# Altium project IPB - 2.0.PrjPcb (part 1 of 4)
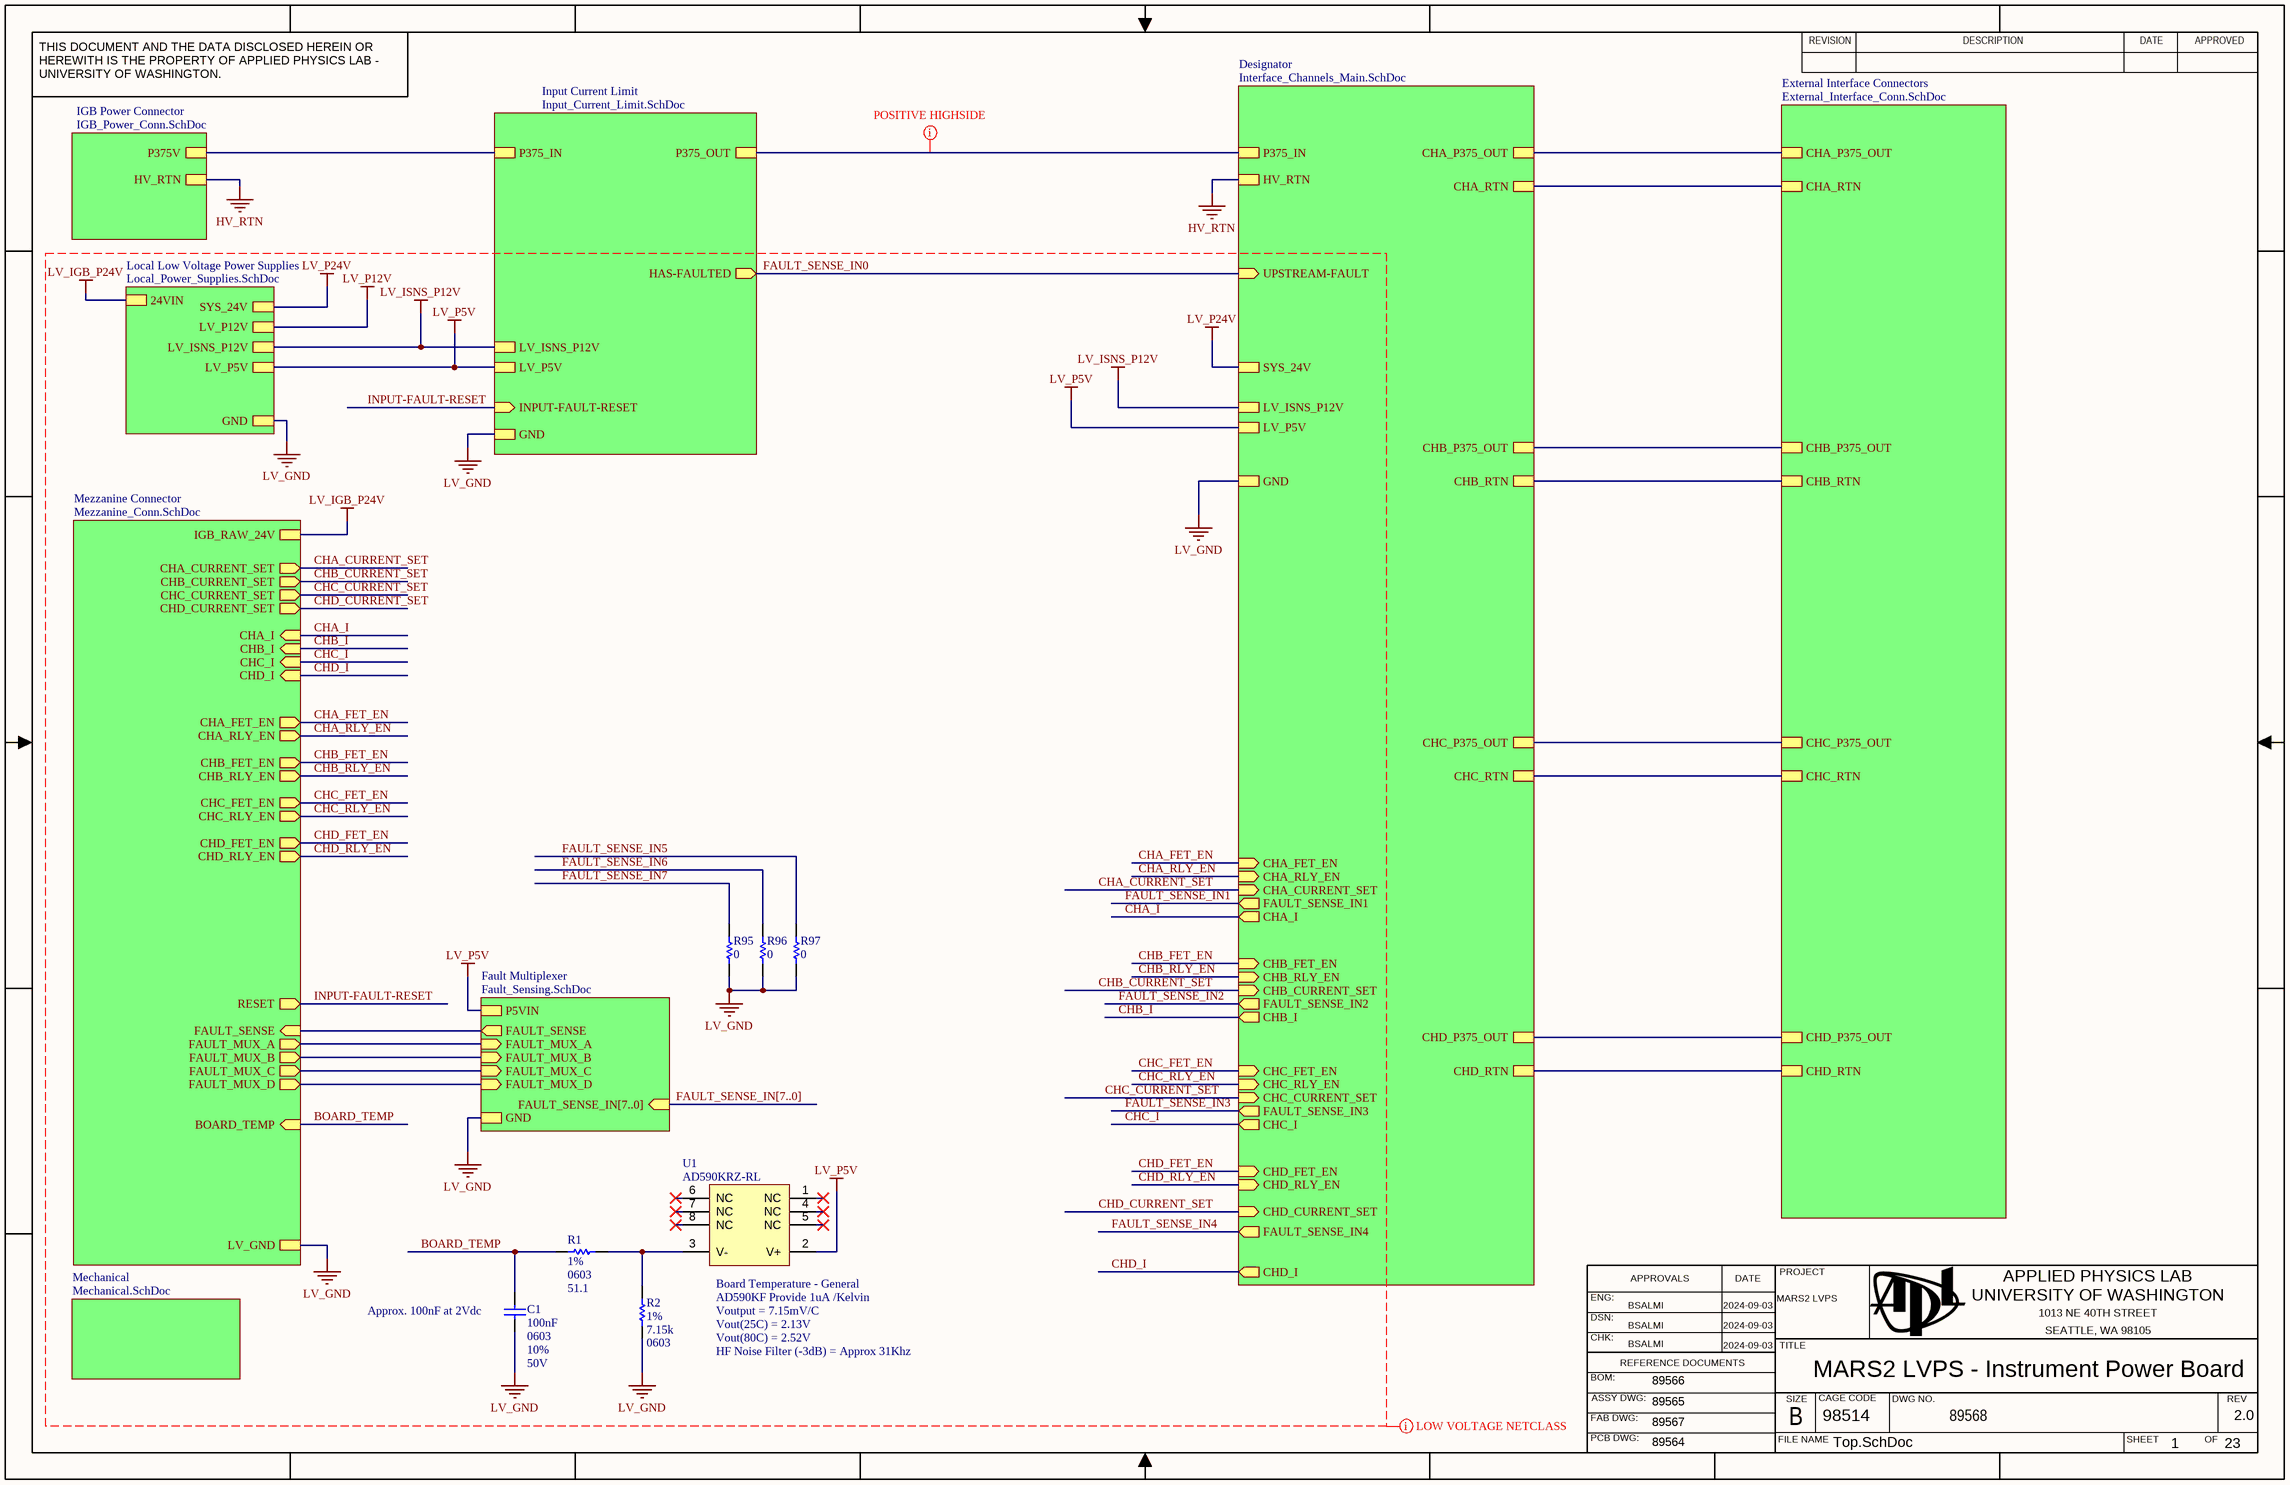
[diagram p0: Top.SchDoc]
Gbl_Cage: 98514; Gbl_CheckedBy: BSALMI; Gbl_CHK_APP_DATE: 2024-09-03; Gbl_DOC_NO_ASSY_DWG: 89565; Gbl_DOC_NO_BOM: 89566; Gbl_DOC_NO_FAB_DWG: 89567; Gbl_DOC_NO_SCH_DWG: 89568; Gbl_DrawnBy: BSALMI; Gbl_DSN_APP_DATE: 2024-09-03; Gbl_ENG_APP_DATE: 2024-09-03; Gbl_Engineer: BSALMI; Gbl_PCB_DWG_NO: 89564; Gbl_Project: MARS2 LVPS; Gbl_Revision: 2.0; GlobalCage: 98514; GlobalProject: MARS2 LVPS; GlobalRevision: 2.0; GlobalSchematicNumber: 89568
23 sheets, 657 parts. Net scope: strictly hierarchical (ports join the sheet entries above them; power ports are local).
Board file: IPB_V2.PcbDoc
Sheets:
  Top.SchDoc
    IGB Power Connector = IGB_Power_Conn.SchDoc
    Input Current Limit = Input_Current_Limit.SchDoc
      Current Sense = Current_Sense.SchDoc
      Current Limit - Configurable = Analog_Current_Limit.SchDoc
      12V to 5V (Linear) - ISNS Power = 12V_to_5V_ISNS_REFOUT.SchDoc
      Channel Logic = FET_CH_Digital_Logic.SchDoc
    Mezzanine Connector = Mezzanine_Conn.SchDoc
    External Interface Connectors = External_Interface_Conn.SchDoc
    Fault Multiplexer = Fault_Sensing.SchDoc
    Local Low Voltage Power Supplies = Local_Power_Supplies.SchDoc
      24 to 12V (DC/DC) = 24V_to_12V_DCDC.SchDoc
      24 to 5V (DC/DC) - 5V Logic = 24V_to_5V_DCDC.SchDoc
    Mechanical = Mechanical.SchDoc
    Designator = Interface_Channels_Main.SchDoc
      Interface Channel A = Interface_Channel.SchDoc
        Overcurrent Current Sense = Current_Sense.SchDoc
        Channel Logic = FET_CH_Digital_Logic.SchDoc
        Current Limit - Configurable = Analog_Current_Limit.SchDoc
        Contactor Driver = Relay_Driver.SchDoc
        Contactor Driver = Relay_Driver.SchDoc
        Anti-Alias Filter = Anti_Alias_Filter.SchDoc
        12V to 5V (Linear) - ISNS Power = 12V_to_5V_ISNS_REFOUT.SchDoc
        Solid State Switches = Solid_State_Switch.SchDoc
          Isolated Gate Drive Power - HIGH = Isolated_Gate_Power_Supplies.SchDoc
          Short Circuit Current Sense = IN310_ISNS.SchDoc
          Short Circuit Logic Intergration = Short-Circuit-Logic-Integration.SchDoc
            MOSFET HIGH Driver = Gate_Driver.SchDoc
      Interface Channel B = Interface_Channel.SchDoc
        Overcurrent Current Sense = Current_Sense.SchDoc
        Channel Logic = FET_CH_Digital_Logic.SchDoc
        Current Limit - Configurable = Analog_Current_Limit.SchDoc
        Contactor Driver = Relay_Driver.SchDoc
        Contactor Driver = Relay_Driver.SchDoc
        Anti-Alias Filter = Anti_Alias_Filter.SchDoc
        12V to 5V (Linear) - ISNS Power = 12V_to_5V_ISNS_REFOUT.SchDoc
        Solid State Switches = Solid_State_Switch.SchDoc
          Isolated Gate Drive Power - HIGH = Isolated_Gate_Power_Supplies.SchDoc
          Short Circuit Current Sense = IN310_ISNS.SchDoc
          Short Circuit Logic Intergration = Short-Circuit-Logic-Integration.SchDoc
            MOSFET HIGH Driver = Gate_Driver.SchDoc
      Interface Channel C = Interface_Channel.SchDoc
        Overcurrent Current Sense = Current_Sense.SchDoc
        Channel Logic = FET_CH_Digital_Logic.SchDoc
        Current Limit - Configurable = Analog_Current_Limit.SchDoc
        Contactor Driver = Relay_Driver.SchDoc
        Contactor Driver = Relay_Driver.SchDoc
        Anti-Alias Filter = Anti_Alias_Filter.SchDoc
        12V to 5V (Linear) - ISNS Power = 12V_to_5V_ISNS_REFOUT.SchDoc
        Solid State Switches = Solid_State_Switch.SchDoc
          Isolated Gate Drive Power - HIGH = Isolated_Gate_Power_Supplies.SchDoc
          Short Circuit Current Sense = IN310_ISNS.SchDoc
          Short Circuit Logic Intergration = Short-Circuit-Logic-Integration.SchDoc
            MOSFET HIGH Driver = Gate_Driver.SchDoc
      Interface Channel D = Interface_Channel.SchDoc
        Overcurrent Current Sense = Current_Sense.SchDoc
        Channel Logic = FET_CH_Digital_Logic.SchDoc
        Current Limit - Configurable = Analog_Current_Limit.SchDoc
        Contactor Driver = Relay_Driver.SchDoc
        Contactor Driver = Relay_Driver.SchDoc
        Anti-Alias Filter = Anti_Alias_Filter.SchDoc
        12V to 5V (Linear) - ISNS Power = 12V_to_5V_ISNS_REFOUT.SchDoc
        Solid State Switches = Solid_State_Switch.SchDoc
          Isolated Gate Drive Power - HIGH = Isolated_Gate_Power_Supplies.SchDoc
          Short Circuit Current Sense = IN310_ISNS.SchDoc
          Short Circuit Logic Intergration = Short-Circuit-Logic-Integration.SchDoc
            MOSFET HIGH Driver = Gate_Driver.SchDoc

## Sheet Top.SchDoc: MARS2 LVPS - Instrument Power Board
size 431 x 279 mm; Organization: ORGANIZATION; Address1: APPLIED PHYSICS LAB; Address2: UNIVERSITY OF WASHINGTON; Address3: 1013 NE 40TH STREET; Address4: SEATTLE, WA 98105; Revision: -; SheetNumber: 1; SheetTotal: 23; ENG_APP_DATE: --/--/--; DSN_APP_DATE: --/--/--; CHK_APP_DATE: --/--/--

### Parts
C1  value 100nF  Case/Package: 0603  Tolerance: 10%  Voltage Rating: 50V  [CAPC1608X90X40ML10T20]  (hidden comment: Capacitor 100nF +/- 10%, 50V, X7R, 0603)
R1  value 51.1  Tolerance: 1%  Case/Package: 0603  [RESC1609X50X30ML08T20]  (hidden comment: Resistor 51R1 +/-1% 0603 100 mW)
R2  value 7.15k  Tolerance: 1%  Case/Package: 0603  [RESC1609X50X30ML08T20]  (hidden comment: Resistor 7K15 +/-1% 0603 100 mW)
R95  value 0  [RESC1608X55X25ML10T15]  (hidden comment: Resistor 0R +/- 5% 0603 100 mW)
R96  value 0  [RESC1608X55X25ML10T15]  (hidden comment: Resistor 0R +/- 5% 0603 100 mW)
R97  value 0  [RESC1608X55X25ML10T15]  (hidden comment: Resistor 0R +/- 5% 0603 100 mW)
U1  AD590KRZ-RL  [ADI-R-8_M]

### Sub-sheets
Designator = Interface_Channels_Main.SchDoc: CHA_P375_OUT, CHB_P375_OUT, CHC_P375_OUT, CHD_P375_OUT, CHA_RTN, CHB_RTN, CHC_RTN, CHD_RTN, P375_IN, HV_RTN, UPSTREAM-FAULT (in), CHD_FET_EN (in), CHD_RLY_EN (in), CHD_CURRENT_SET (in), FAULT_SENSE_IN4 (out), CHD_I (out), CHC_FET_EN (in), CHC_RLY_EN (in), CHC_CURRENT_SET (in), FAULT_SENSE_IN3 (out), CHC_I (out), CHB_FET_EN (in), CHB_RLY_EN (in), CHB_CURRENT_SET (in), FAULT_SENSE_IN2 (out), CHB_I (out), CHA_FET_EN (in), CHA_RLY_EN (in), CHA_CURRENT_SET (in), FAULT_SENSE_IN1 (out), CHA_I (out), SYS_24V, LV_ISNS_P12V, LV_P5V, GND
External Interface Connectors = External_Interface_Conn.SchDoc: CHA_P375_OUT, CHB_P375_OUT, CHC_P375_OUT, CHD_P375_OUT, CHA_RTN, CHB_RTN, CHC_RTN, CHD_RTN
Fault Multiplexer = Fault_Sensing.SchDoc: FAULT_SENSE (out), FAULT_SENSE_IN[7..0] (in), FAULT_MUX_D (in), FAULT_MUX_B (in), FAULT_MUX_A (in), FAULT_MUX_C (in), GND, P5VIN
IGB Power Connector = IGB_Power_Conn.SchDoc: P375V, HV_RTN
Input Current Limit = Input_Current_Limit.SchDoc: P375_IN, P375_OUT, HAS-FAULTED (out), INPUT-FAULT-RESET (in), LV_P5V, LV_ISNS_P12V, GND
Local Low Voltage Power Supplies = Local_Power_Supplies.SchDoc: 24VIN, SYS_24V, LV_P12V, LV_ISNS_P12V, LV_P5V, GND
Mechanical = Mechanical.SchDoc: no entries
Mezzanine Connector = Mezzanine_Conn.SchDoc: CHB_CURRENT_SET (out), CHA_CURRENT_SET (out), CHC_CURRENT_SET (out), CHD_CURRENT_SET (out), CHB_I (in), CHD_I (in), CHC_I (in), CHA_I (in), BOARD_TEMP (in), FAULT_SENSE (in), RESET (out), CHA_RLY_EN (out), CHC_RLY_EN (out), CHA_FET_EN (out), CHC_FET_EN (out), CHD_FET_EN (out), CHD_RLY_EN (out), CHB_RLY_EN (out), CHB_FET_EN (out), FAULT_MUX_A (out), FAULT_MUX_B (out), FAULT_MUX_C (out), FAULT_MUX_D (out), LV_GND, IGB_RAW_24V

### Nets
HV_RTN: sheet IGB Power Connector/HV_RTN, sheet Designator/HV_RTN  [project net N187]
LV_GND: C1.1 R2.1 R95.1 R96.1 R97.1 ; sheet Input Current Limit/GND, sheet Mezzanine Connector/LV_GND, sheet Fault Multiplexer/GND, sheet Local Low Voltage Power Supplies/GND, sheet Designator/GND
LV_IGB_P24V: sheet Mezzanine Connector/IGB_RAW_24V, sheet Local Low Voltage Power Supplies/24VIN
LV_ISNS_P12V: sheet Input Current Limit/LV_ISNS_P12V, sheet Local Low Voltage Power Supplies/LV_ISNS_P12V, sheet Designator/LV_ISNS_P12V
LV_P5V: U1.2(V+) ; sheet Input Current Limit/LV_P5V, sheet Fault Multiplexer/P5VIN, sheet Local Low Voltage Power Supplies/LV_P5V, sheet Designator/LV_P5V
LV_P24V: sheet Local Low Voltage Power Supplies/SYS_24V, sheet Designator/SYS_24V  [project net COIL_DRV_HIGH]
BOARD_TEMP: C1.2 R1.1 ; sheet Mezzanine Connector/BOARD_TEMP
CHA_CURRENT_SET: sheet Mezzanine Connector/CHA_CURRENT_SET, sheet Designator/CHA_CURRENT_SET
CHA_FET_EN: sheet Mezzanine Connector/CHA_FET_EN, sheet Designator/CHA_FET_EN
CHA_I: sheet Mezzanine Connector/CHA_I, sheet Designator/CHA_I
CHA_RLY_EN: sheet Mezzanine Connector/CHA_RLY_EN, sheet Designator/CHA_RLY_EN
CHB_CURRENT_SET: sheet Mezzanine Connector/CHB_CURRENT_SET, sheet Designator/CHB_CURRENT_SET
CHB_FET_EN: sheet Mezzanine Connector/CHB_FET_EN, sheet Designator/CHB_FET_EN
CHB_I: sheet Mezzanine Connector/CHB_I, sheet Designator/CHB_I
CHB_RLY_EN: sheet Mezzanine Connector/CHB_RLY_EN, sheet Designator/CHB_RLY_EN
CHC_CURRENT_SET: sheet Mezzanine Connector/CHC_CURRENT_SET, sheet Designator/CHC_CURRENT_SET
CHC_FET_EN: sheet Mezzanine Connector/CHC_FET_EN, sheet Designator/CHC_FET_EN
CHC_I: sheet Mezzanine Connector/CHC_I, sheet Designator/CHC_I
CHC_RLY_EN: sheet Mezzanine Connector/CHC_RLY_EN, sheet Designator/CHC_RLY_EN
CHD_CURRENT_SET: sheet Mezzanine Connector/CHD_CURRENT_SET, sheet Designator/CHD_CURRENT_SET
CHD_FET_EN: sheet Mezzanine Connector/CHD_FET_EN, sheet Designator/CHD_FET_EN
CHD_I: sheet Mezzanine Connector/CHD_I, sheet Designator/CHD_I
CHD_RLY_EN: sheet Mezzanine Connector/CHD_RLY_EN, sheet Designator/CHD_RLY_EN
FAULT_MUX_A: sheet Mezzanine Connector/FAULT_MUX_A, sheet Fault Multiplexer/FAULT_MUX_A
FAULT_MUX_B: sheet Mezzanine Connector/FAULT_MUX_B, sheet Fault Multiplexer/FAULT_MUX_B
FAULT_MUX_C: sheet Mezzanine Connector/FAULT_MUX_C, sheet Fault Multiplexer/FAULT_MUX_C
FAULT_MUX_D: sheet Mezzanine Connector/FAULT_MUX_D, sheet Fault Multiplexer/FAULT_MUX_D
FAULT_SENSE: sheet Mezzanine Connector/FAULT_SENSE, sheet Fault Multiplexer/FAULT_SENSE
FAULT_SENSE_IN0: sheet Input Current Limit/HAS-FAULTED, sheet Designator/UPSTREAM-FAULT
FAULT_SENSE_IN5: R97.2
FAULT_SENSE_IN6: R96.2
FAULT_SENSE_IN7: R95.2
INPUT-FAULT-RESET: sheet Input Current Limit/INPUT-FAULT-RESET, sheet Mezzanine Connector/RESET
P187: sheet IGB Power Connector/P375V, sheet Input Current Limit/P375_IN
NetD1_A_1: sheet External Interface Connectors/CHA_RTN, sheet Designator/CHA_RTN
NetD1_A_4: sheet External Interface Connectors/CHA_P375_OUT, sheet Designator/CHA_P375_OUT
NetD1_B_1: sheet External Interface Connectors/CHB_RTN, sheet Designator/CHB_RTN
NetD1_B_4: sheet External Interface Connectors/CHB_P375_OUT, sheet Designator/CHB_P375_OUT
NetD1_C_1: sheet External Interface Connectors/CHC_RTN, sheet Designator/CHC_RTN
NetD1_C_4: sheet External Interface Connectors/CHC_P375_OUT, sheet Designator/CHC_P375_OUT
NetD1_D_1: sheet External Interface Connectors/CHD_RTN, sheet Designator/CHD_RTN
NetD1_D_4: sheet External Interface Connectors/CHD_P375_OUT, sheet Designator/CHD_P375_OUT
NetR1_2: R1.2 R2.2 U1.3(V-)
NetU4_A_3: sheet Input Current Limit/P375_OUT, sheet Designator/P375_IN

Not connected (* = marked no-connect by the designer): U1 1(NC)* 4(NC)* 5(NC)* 6(NC)* 7(NC)* 8(NC)*

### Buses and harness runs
bus FAULT_SENSE_IN[7..0] = sheet Fault Multiplexer/FAULT_SENSE_IN[7..0]

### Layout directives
net class LV_NETCLASS: BOARD_TEMP, CHA_CURRENT_SET, CHA_FET_EN, CHA_I, CHA_RLY_EN, CHB_CURRENT_SET, CHB_FET_EN, CHB_I, CHB_RLY_EN, CHC_CURRENT_SET, CHC_FET_EN, CHC_I, CHC_RLY_EN, CHD_CURRENT_SET, CHD_FET_EN, CHD_I, CHD_RLY_EN, FAULT_SENSE_IN0, FAULT_SENSE_IN1, FAULT_SENSE_IN2, FAULT_SENSE_IN3, FAULT_SENSE_IN4, FAULT_SENSE_IN5, FAULT_SENSE_IN6, FAULT_SENSE_IN7, FAULT_SENSE_IN[7..0], INPUT-FAULT-RESET, LV_GND, LV_IGB_P24V, LV_ISNS_P12V, LV_P5V, LV_P12V, LV_P24V
net class POSITIVE HIGHSIDE: NetU4_A_3

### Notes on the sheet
- (near U1) Board Temperature - General
- (near U1) AD590KF Provide 1uA /Kelvin
- (near C1) Approx. 100nF at 2Vdc
- Voutput = 7.15mV/C
- Vout(25C) = 2.13V
- Vout(80C) = 2.52V
- HF Noise Filter (-3dB) = Approx 31Khz

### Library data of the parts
C1 = CMP-001-00206-10: Chip Capacitor, 100nF, +/- 10%, 50 V, X7R 0603 (1608 Metric); Capacitor Type: Ceramic
R1 = CMP-009-01135-2: Chip Resistor, 51.1 Ohm, +/- 1%, 0.1 W, -55 to 155 degC, 0603 (1608 Metric); Voltage Rating: 75V; Power: 100mW; Decade: 10
R2 = CMP-009-00865-5: Chip Resistor, 7.15k Ohm, +/- 1%, 0.1 W, -55 to 155 degC, 0603 (1608 Metric); Voltage Rating: 75V; Power: 100mW; Decade: 1k
R95-R97 = CMP-009-00006-7: Chip Resistor, 0 Ohm, 0.1 W, -55 to 155 degC, 0603 (1608 Metric); Voltage Rating: 50V; Power: 100mW
U1 = CMP-010-00032-1: Temp Sensor Analog 8-Pin SOIC N T/R; Max Supply Voltage: 30V; Min Supply Voltage: 4V

## Sheet IGB_Power_Conn.SchDoc: MARS2 - IPB - IGB Power Conn
size 431 x 279 mm; Organization: ORGANIZATION; Address1: APPLIED PHYSICS LAB; Address2: UNIVERSITY OF WASHINGTON; Address3: 1013 NE 40TH STREET; Address4: SEATTLE, WA 98105; Revision: -; SheetNumber: 2; SheetTotal: 23; ENG_APP_DATE: --/--/--; DSN_APP_DATE: --/--/--; CHK_APP_DATE: --/--/--
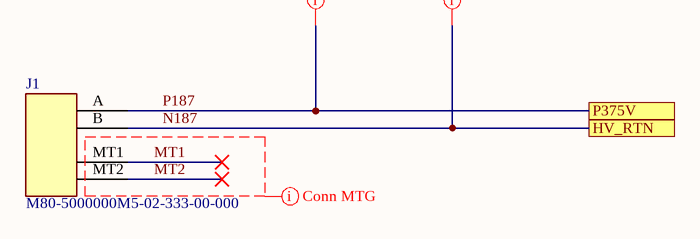
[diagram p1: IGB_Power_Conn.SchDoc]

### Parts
J1  M80-5000000M5-02-333-00-000  [FP-M80-5000000M5-02-333-0-MFG]

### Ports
HV_RTN, P375V

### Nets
N187: J1.B ; port HV_RTN
MT1: J1.MT1(MNT_1)  [project net MT1_2]
MT2: J1.MT2(MNT_2)  [project net MT2_2]
P187: J1.A ; port P375V

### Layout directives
net class P187_REF: P187
net class N187_REF: N187
net class Mounting Hole: MT1, MT2

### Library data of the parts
J1 = CMP-002-00075-7: Conn Header R/a 2POS 4MM; Manufacturer: Harwin; Number of Positions: 2; Pitch: 4.00mm; Current Rating: 40A; Contact Resistance: 25mR; Voltage Rating: 800V; Gender: Male; Insulation Resistance: 100MR

## Sheet Input_Current_Limit.SchDoc: MARS2 - IPB - Input Current Limit
size 431 x 279 mm; Organization: ORGANIZATION; Address1: APPLIED PHYSICS LAB; Address2: UNIVERSITY OF WASHINGTON; Address3: 1013 NE 40TH STREET; Address4: SEATTLE, WA 98105; Revision: -; SheetNumber: 4; SheetTotal: 23; ENG_APP_DATE: --/--/--; DSN_APP_DATE: --/--/--; CHK_APP_DATE: --/--/--
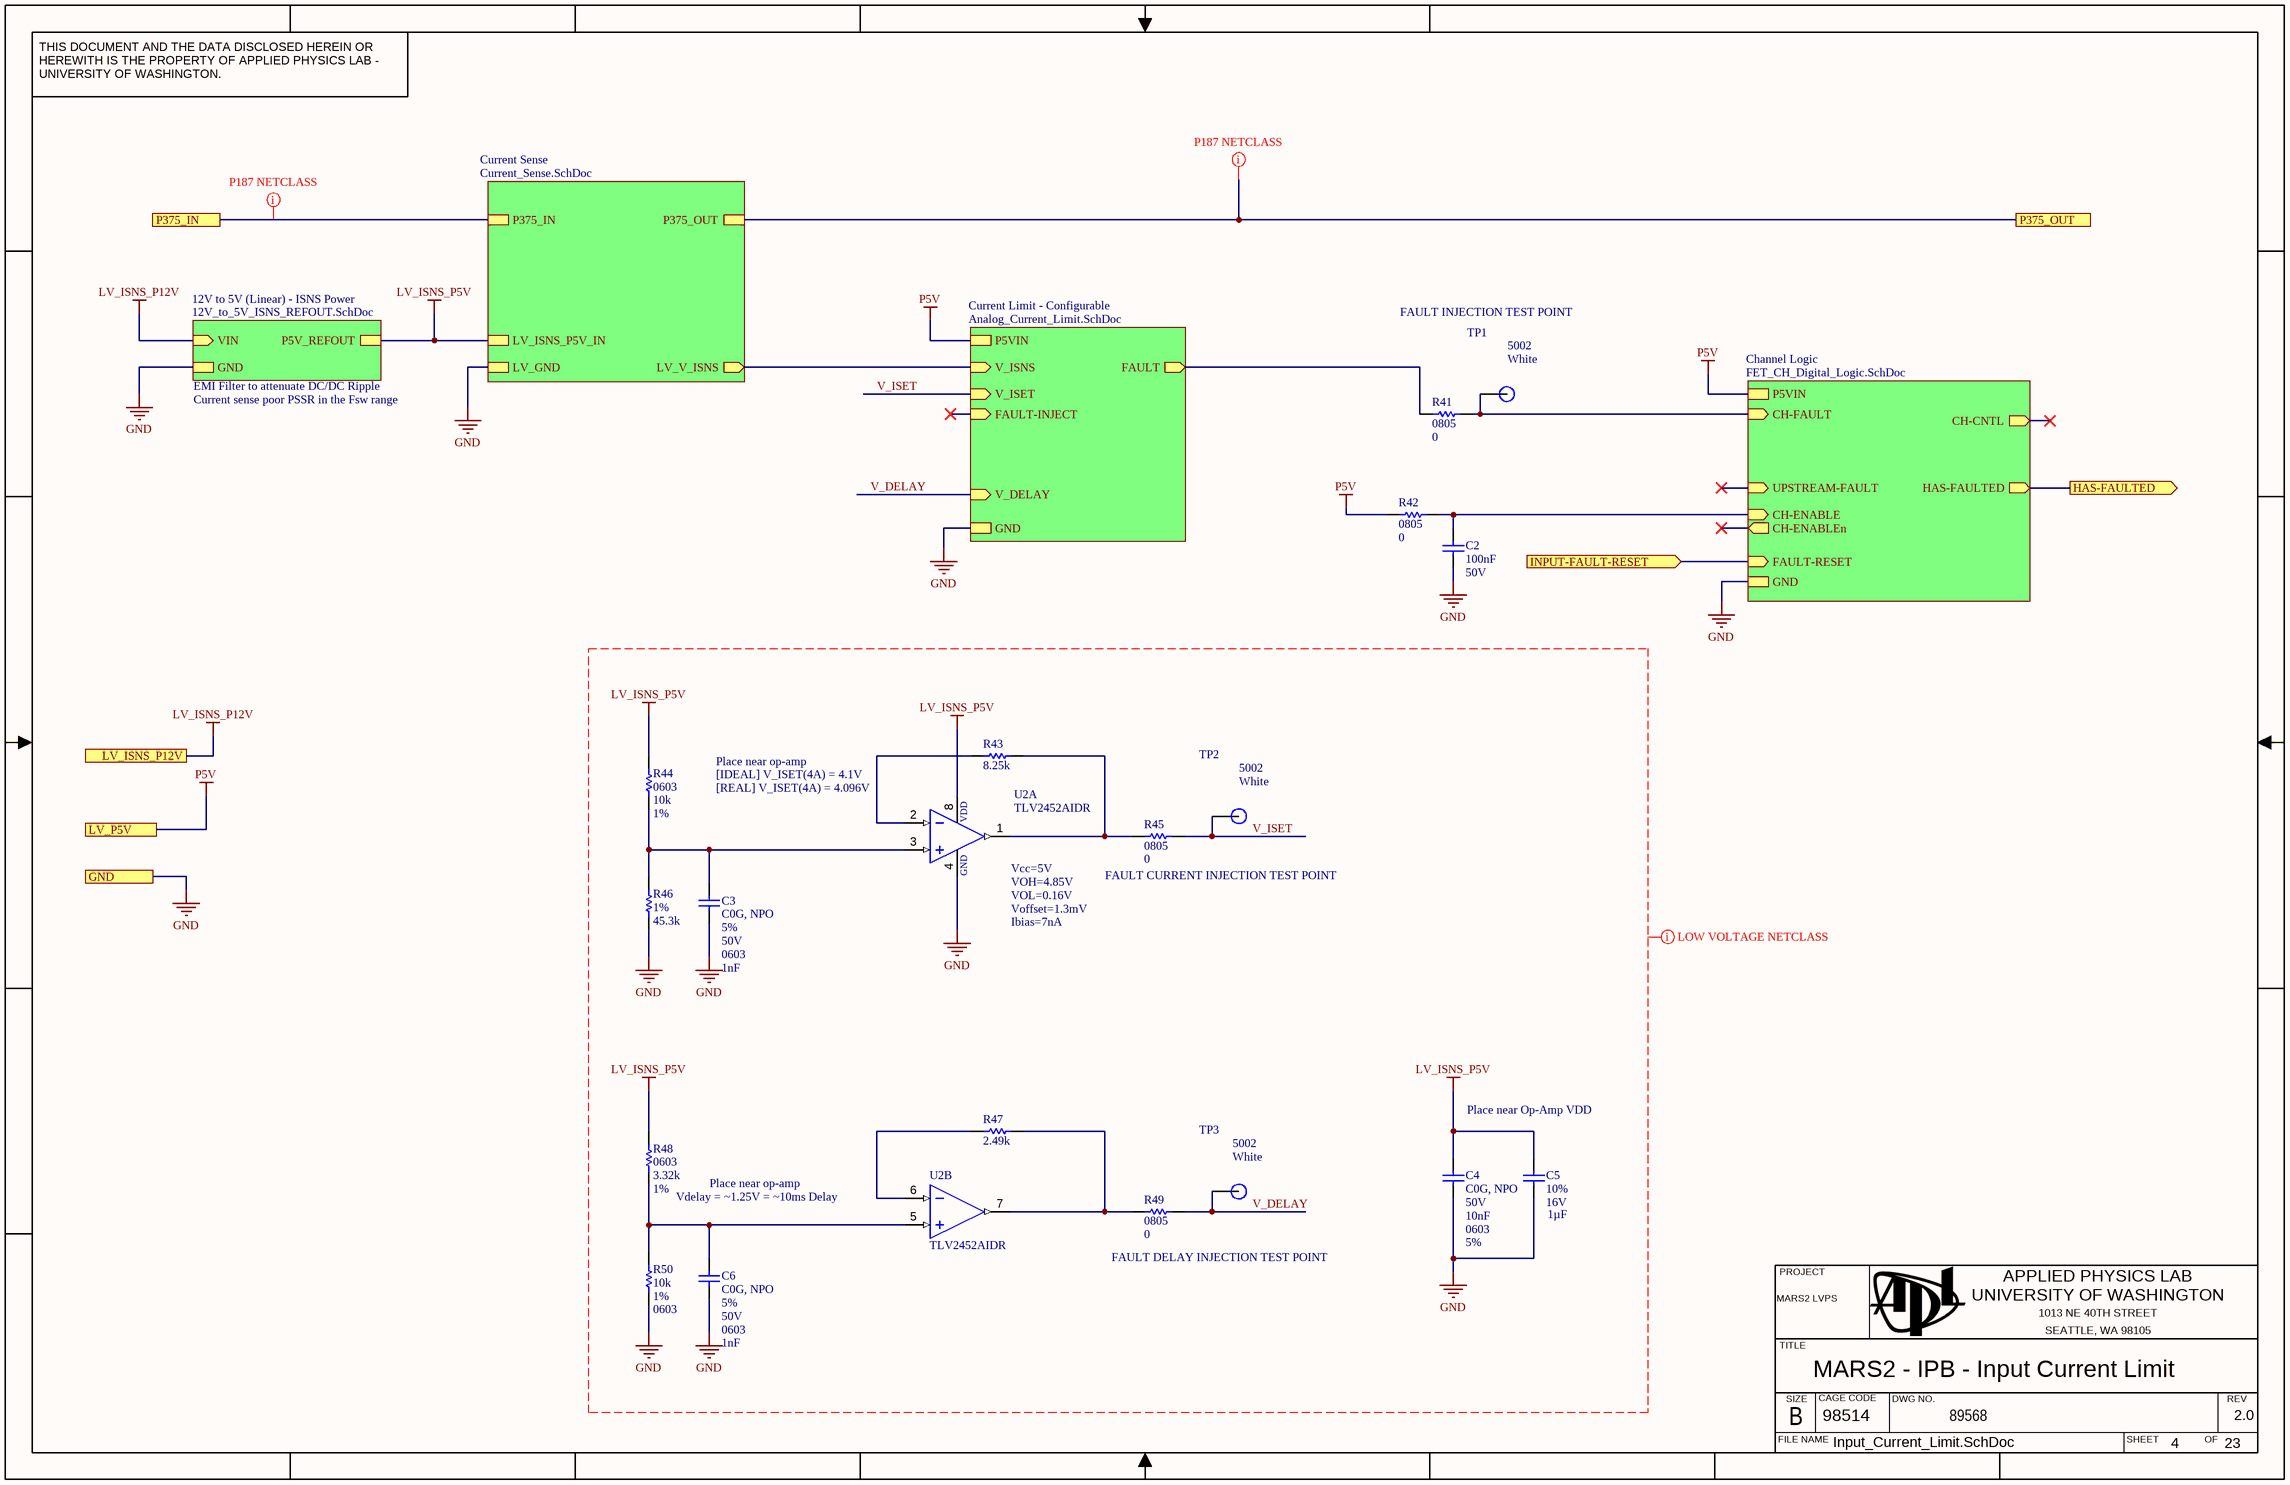
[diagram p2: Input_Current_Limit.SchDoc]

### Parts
C2  value 100nF  Voltage Rating: 50V  [CAPC2013X95X50ML10T25]  (hidden comment: Capacitor 100 nF +/-10% 50 V 0805)
C3  Dielectric: C0G, NPO  Tolerance: 5%  Voltage Rating: 50V  Case/Package: 0603  Capacitance: 1nF  [CAPC1608X90X40ML10T20]  (hidden comment: Capacitor 1nF +/- 5%, 50V, C0G, 0603)
C4  Dielectric: C0G, NPO  Voltage Rating: 50V  Capacitance: 10nF  Case/Package: 0603  Tolerance: 5%  [CAPC1608X90X40ML10T20]  (hidden comment: Capacitor 10nF +/- 5%, 50V, C0G, 0603)
C5  value 1µF  Tolerance: 10%  Voltage Rating: 16V  [CAPC1608X94X35NL15T15]  (hidden comment: Capacitor 1 uF +/- 10% 16 V 0603)
C6  Dielectric: C0G, NPO  Tolerance: 5%  Voltage Rating: 50V  Case/Package: 0603  Capacitance: 1nF  [CAPC1608X90X40ML10T20]  (hidden comment: Capacitor 1nF +/- 5%, 50V, C0G, 0603)
R41  value 0  Case/Package: 0805  [RESC2013X60X35ML10T20]  (hidden comment: Resistor 0R +/- 5% 0805 125 mW)
R42  value 0  Case/Package: 0805  [RESC2013X60X35ML10T20]  (hidden comment: Resistor 0R +/- 5% 0805 125 mW)
R43  value 8.25k  [RESC1609X50X30ML08T20]  (hidden comment: Resistor 8K25 +/-1% 0603 100 mW)
R44  value 10k  Case/Package: 0603  Tolerance: 1%  [RESC1608X55X25ML10T15]  (hidden comment: Resistor 10k +/-1% 0603 100 mW)
R45  value 0  Case/Package: 0805  [RESC2013X60X35ML10T20]  (hidden comment: Resistor 0R +/- 5% 0805 125 mW)
R46  value 45.3k  Tolerance: 1%  [RESC1608X55X25ML10T15]  (hidden comment: Resistor 45K3 +/-1% 0603 100 mW)
R47  value 2.49k  [RESC1609X50X30ML08T20]  (hidden comment: Resistor 2K49 +/-1% 0603 100 mW)
R48  value 3.32k  Case/Package: 0603  Tolerance: 1%  [RESC1609X50X30ML08T20]  (hidden comment: Resistor 3K32 +/-1% 0603 100 mW)
R49  value 0  Case/Package: 0805  [RESC2013X60X35ML10T20]  (hidden comment: Resistor 0R +/- 5% 0805 125 mW)
R50  value 10k  Tolerance: 1%  Case/Package: 0603  [RESC1608X55X25ML10T15]  (hidden comment: Resistor 10k +/-1% 0603 100 mW)
TP1  5002  Color: White  [Keystone 5002]
TP2  5002  Color: White  [Keystone 5002]
TP3  5002  Color: White  [Keystone 5002]
U2  TLV2452AIDR  [D0008A_L]  (parts A,B of 2)

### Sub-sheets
12V to 5V (Linear) - ISNS Power = 12V_to_5V_ISNS_REFOUT.SchDoc: VIN (in), P5V_REFOUT, GND
Channel Logic = FET_CH_Digital_Logic.SchDoc: CH-FAULT (in), CH-CNTL (out), UPSTREAM-FAULT (in), CH-ENABLE (in), HAS-FAULTED (out), FAULT-RESET (in), CH-ENABLEn (out), GND, P5VIN
Current Limit - Configurable = Analog_Current_Limit.SchDoc: V_ISNS (in), FAULT (out), V_ISET (in), V_DELAY (in), GND, P5VIN, FAULT-INJECT (in)
Current Sense = Current_Sense.SchDoc: P375_IN, P375_OUT, LV_V_ISNS (out), LV_ISNS_P5V_IN, LV_GND

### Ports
GND, HAS-FAULTED (out), INPUT-FAULT-RESET (in), LV_ISNS_P12V, LV_P5V, P375_IN, P375_OUT

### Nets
GND: C2.1 C3.2 C4.1 C5.1 C6.2 R46.1 R50.1 U2.4(GND) ; port GND, sheet Current Sense/LV_GND, sheet Current Limit - Configurable/GND, sheet 12V to 5V (Linear) - ISNS Power/GND, sheet Channel Logic/GND  [project net LV_GND]
LV_ISNS_P5V: C4.2 C5.2 R44.1 R48.1 U2.8(VDD+) ; sheet Current Sense/LV_ISNS_P5V_IN, sheet 12V to 5V (Linear) - ISNS Power/P5V_REFOUT
LV_ISNS_P12V: port LV_ISNS_P12V, sheet 12V to 5V (Linear) - ISNS Power/VIN
P5V: R42.2 ; port LV_P5V, sheet Current Limit - Configurable/P5VIN, sheet Channel Logic/P5VIN  [project net LV_P5V]
ACTIVE-FAULT: R41.1 TP1.1 ; sheet Channel Logic/CH-FAULT
CH-ENABLE: C2.2 R42.1 ; sheet Channel Logic/CH-ENABLE
FAULT_SENSE_IN0: port HAS-FAULTED, sheet Channel Logic/HAS-FAULTED
INPUT-FAULT-RESET: port INPUT-FAULT-RESET, sheet Channel Logic/FAULT-RESET
P187: port P375_IN, sheet Current Sense/P375_IN
V_DELAY: R49.1 TP3.1 ; sheet Current Limit - Configurable/V_DELAY
V_ISET: R45.1 TP2.1 ; sheet Current Limit - Configurable/V_ISET
NetC3_1: C3.1 R44.2 R46.2 U2.3(IN1+)
NetC6_1: C6.1 R48.2 R50.2 U2.5(IN2+)
NetR41_2: R41.2 ; sheet Current Limit - Configurable/FAULT
NetR43_1: R43.1 U2.2(IN1-)
NetR43_2: R43.2 R45.2 U2.1(OUT1)
NetR47_1: R47.1 U2.6(IN2-)
NetR47_2: R47.2 R49.2 U2.7(OUT2)
NetR69_A_1: sheet Current Sense/LV_V_ISNS, sheet Current Limit - Configurable/V_ISNS
NetU4_A_3: port P375_OUT, sheet Current Sense/P375_OUT

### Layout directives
net class P187_REF: NetU4_A_3, P187
net class LV_NETCLASS: GND, LV_ISNS_P5V, V_DELAY, V_ISET

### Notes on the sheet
- FAULT INJECTION TEST POINT
- EMI Filter to attenuate DC/DC Ripple
- Current sense poor PSSR in the Fsw range
- Place near op-amp
- [IDEAL] V_ISET(4A) = 4.1V
- [REAL] V_ISET(4A) = 4.096V
- (near U2) VOL=0.16V
- (near U2) Vcc=5V
- (near U2) VOH=4.85V
- FAULT CURRENT INJECTION TEST POINT
- Voffset=1.3mV
- Ibias=7nA
- Place near Op-Amp VDD
- (near R48) Vdelay =
  .25V =
  0ms Delay
- FAULT DELAY INJECTION TEST POINT

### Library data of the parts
C2 = CMP-001-00018-16: Chip Capacitor, 100 nF, +/- 10%, 50 V, 0805 (2012 Metric); Capacitor Type: Ceramic
C3 C6 = CMP-001-00153-10: Chip Capacitor, 1nF, +/- 5%, 50 V, C0G 0603 (1608 Metric); Capacitor Type: Ceramic
C4 = CMP-001-00166-10: Chip Capacitor, 10nF, +/- 5%, 50 V, C0G 0603 (1608 Metric); Capacitor Type: Ceramic
C5 = CMP-001-00003-15: Chip Capacitor, 1 uF, +/- 10%, 16 V, 0603 (1608 Metric); Capacitor Type: Ceramic; Decade: 1uF
R41 R42 R45 R49 = CMP-009-00007-7: Chip Resistor, 0 Ohm, 0.125 W, -55 to 155 degC, 0805 (2012 Metric); Power: 125mW; Voltage Rating: 50V
R43 = CMP-009-00871-5: Chip Resistor, 8.25k Ohm, +/- 1%, 0.1 W, -55 to 155 degC, 0603 (1608 Metric); Power: 100mW; Decade: 1k; Voltage Rating: 75V
R44 R50 = CMP-009-00017-8: Chip Resistor, 10 KOhm, +/- 1%, 01 W, -55 to 155 degC, 0603 (1608 Metric); Voltage Rating: 50V; Power: 100mW
R46 = CMP-009-00997-4: Chip Resistor, 45.3k Ohm, +/- 1%, 0.1 W, -55 to 155 degC, 0603 (1608 Metric); Voltage Rating: 75V; Decade: 10k; Power: 100mW
R47 = CMP-009-00822-5: Chip Resistor, 2.49k Ohm, +/- 1%, 0.1 W, -55 to 155 degC, 0603 (1608 Metric); Decade: 1k; Voltage Rating: 75V; Power: 100mW
R48 = CMP-009-00834-5: Chip Resistor, 3.32k Ohm, +/- 1%, 0.1 W, -55 to 155 degC, 0603 (1608 Metric); Voltage Rating: 75V; Decade: 1k; Power: 100mW
TP1-TP3 = CMP-002-00083-13: PC TEST POINT MINIATURE WHITE; Manufacturer: Keystone
U2 = CMP-014-00006-4: TLV2452A Dual 23-UA 220-KHZ Rail; Gain Bandwidth Product: 220kHz; Amplifier Type: GENERAL PURPOSE; Number of Channels: 2; Voltage Gain: 103dB; Input Bias Current: 5nA; Max Dual Supply Voltage: 3V; Output Current: 10mA; Max Power Dissipation: 710mW; Max Supply Voltage: 6V; Common Mode Rejection Ratio: 70dB; Min Supply Voltage: 2.7V; Input Offset Voltage (Vos): 1mV; Slew Rate: 0.11V/µs; Min Dual Supply Voltage: 1.35V; Nominal Supply Current: 84uA

## Sheet Current_Sense.SchDoc: MARS2 - IPB - Current Sense
size 431 x 279 mm; Organization: ORGANIZATION; Address1: APPLIED PHYSICS LAB; Address2: UNIVERSITY OF WASHINGTON; Address3: 1013 NE 40TH STREET; Address4: SEATTLE, WA 98105; Revision: -; SheetNumber: 5; SheetTotal: 23; ENG_APP_DATE: --/--/--; DSN_APP_DATE: --/--/--; CHK_APP_DATE: --/--/--
Used 5 times, as channels Input Current Limit/Current Sense, Designator/Interface Channel A/Overcurrent Current Sense, Designator/Interface Channel B/Overcurrent Current Sense, Designator/Interface Channel C/Overcurrent Current Sense, Designator/Interface Channel D/Overcurrent Current Sense. Parts and nets are listed once, with the designators drawn on the sheet.
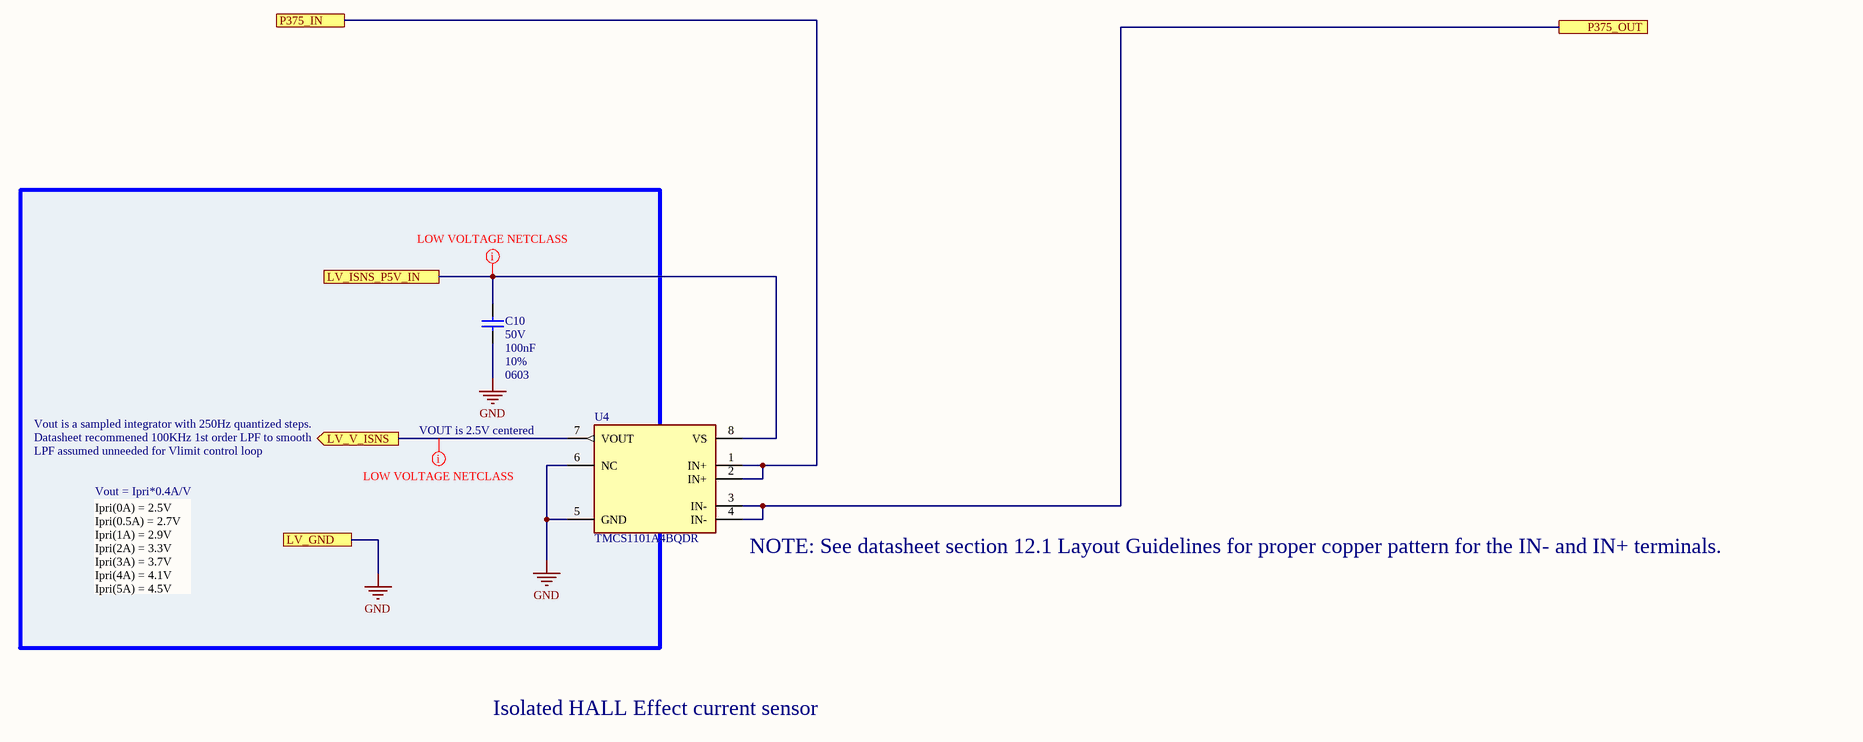
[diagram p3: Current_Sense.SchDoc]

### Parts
C10  value 100nF  Voltage Rating: 50V  Tolerance: 10%  Case/Package: 0603  [CAPC1608X90X40ML10T20]  (hidden comment: Capacitor 100nF +/- 10%, 50V, X7R, 0603)
U4  TMCS1101A4BQDR  [FP-D0008A-IPC_B]

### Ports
LV_GND, LV_ISNS_P5V_IN, LV_V_ISNS (out), P375_IN, P375_OUT

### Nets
GND: C10.2 U4.5(GND) U4.6(NC) ; port LV_GND
LV_ISNS_P5V_IN: C10.1 U4.8(VS) ; port LV_ISNS_P5V_IN
LV_V_ISNS: U4.7(VOUT) ; port LV_V_ISNS
P375_IN: U4.1(IN+) U4.2(IN+) ; port P375_IN
P375_OUT: U4.3(IN-) U4.4(IN-) ; port P375_OUT

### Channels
Input Current Limit/Current Sense: designators end in _A; ports LV_GND=LV_GND LV_ISNS_P5V_IN=LV_ISNS_P5V LV_V_ISNS=NetR69_A_1 P375_IN=P187 P375_OUT=NetU4_A_3
Designator/Interface Channel A/Overcurrent Current Sense: designators end in _B; ports LV_GND=LV_GND LV_ISNS_P5V_IN=NetC10_B_1 LV_V_ISNS=CH-I_Interface Channel A P375_IN=NetU4_A_3 P375_OUT=NetC59_A_1
Designator/Interface Channel B/Overcurrent Current Sense: designators end in _C; ports LV_GND=LV_GND LV_ISNS_P5V_IN=NetC10_C_1 LV_V_ISNS=CH-I_Interface Channel B P375_IN=NetU4_A_3 P375_OUT=NetC59_B_1
Designator/Interface Channel C/Overcurrent Current Sense: designators end in _D; ports LV_GND=LV_GND LV_ISNS_P5V_IN=NetC10_D_1 LV_V_ISNS=CH-I_Interface Channel C P375_IN=NetU4_A_3 P375_OUT=NetC59_C_1
Designator/Interface Channel D/Overcurrent Current Sense: designators end in _E; ports LV_GND=LV_GND LV_ISNS_P5V_IN=NetC10_E_1 LV_V_ISNS=CH-I_Interface Channel D P375_IN=NetU4_A_3 P375_OUT=NetC59_D_1

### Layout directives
net class LV_NETCLASS: LV_ISNS_P5V, NetR69_A_1

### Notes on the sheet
- Datasheet recommened 100KHz 1st order LPF to smooth
- Vout is a sampled integrator with 250Hz quantized steps.
- LPF assumed unneeded for Vlimit control loop
- (near U4) VOUT is 2.5V centered
- Vout = Ipri*0.4A/V
- Ipri(0A) = 2.5V
  Ipri(0.5A) = 2.7V
  Ipri(1A) = 2.9V
  Ipri(2A) = 3.3V
  Ipri(3A) = 3.7V
  Ipri(4A) = 4.1V
  Ipri(5A) = 4.5V
- (near U4) NOTE: See datasheet section 12.1 Layout Guidelines for proper copper pattern for the IN- and IN+ terminals.
- Isolated HALL Effect current sensor

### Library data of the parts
C10 = CMP-001-00206-10: as C1 on sheet Top
U4 = CMP-010-00025-5: Precision isolated bidirectional current sensor with Vsupply ratiometric reference 8-SOIC -40 to 125; Alt PN: TMCS1101A4BQDRQ1; Accuracy: 0.5%; Max Supply Current: 6mA; Sensing Method: Hall Effect; Current Sensing: 5.6A; Linearity: 0.05%; Frequency: 80kHz; Sensitivity: 400mV/A; Number of Channels: 1; Response Time: 6.5us

## Sheet Analog_Current_Limit.SchDoc: MARS2 - IPB - Analog Current Limit
size 431 x 279 mm; Organization: ORGANIZATION; Address1: APPLIED PHYSICS LAB; Address2: UNIVERSITY OF WASHINGTON; Address3: 1013 NE 40TH STREET; Address4: SEATTLE, WA 98105; Revision: -; SheetNumber: 6; SheetTotal: 23; ENG_APP_DATE: --/--/--; DSN_APP_DATE: --/--/--; CHK_APP_DATE: --/--/--
Used 5 times, as channels Input Current Limit/Current Limit - Configurable, Designator/Interface Channel A/Current Limit - Configurable, Designator/Interface Channel B/Current Limit - Configurable, Designator/Interface Channel C/Current Limit - Configurable, Designator/Interface Channel D/Current Limit - Configurable. Parts and nets are listed once, with the designators drawn on the sheet.
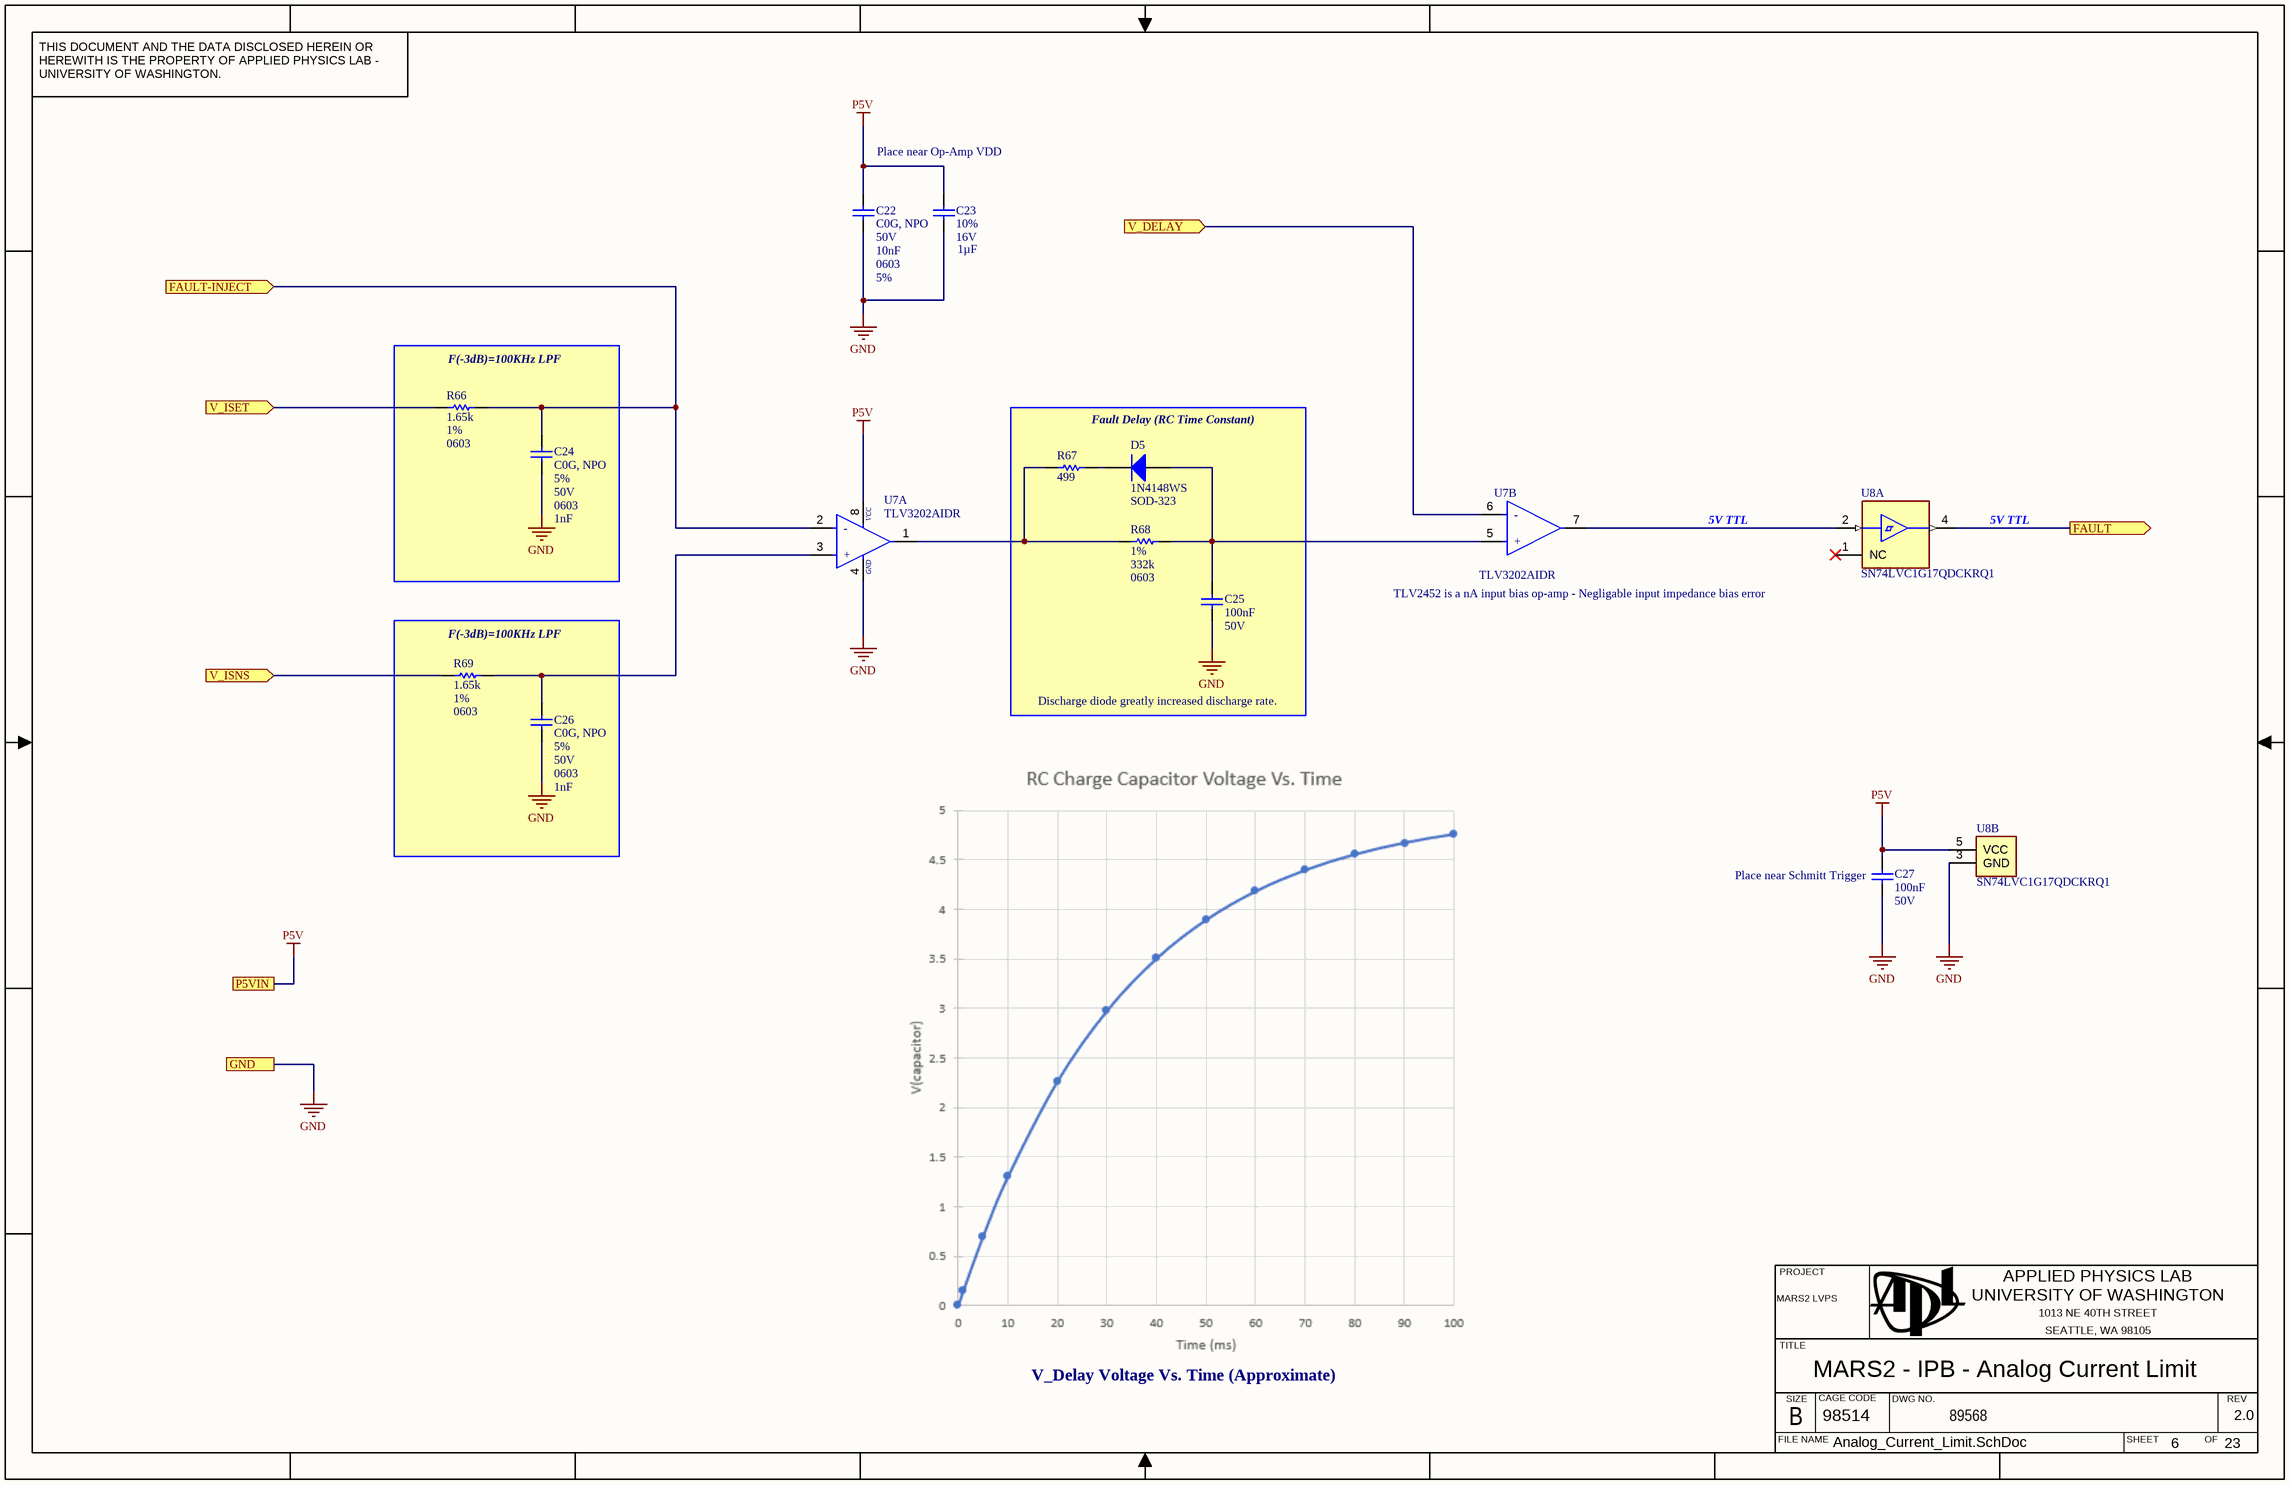
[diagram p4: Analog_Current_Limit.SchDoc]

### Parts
C22  Dielectric: C0G, NPO  Voltage Rating: 50V  Capacitance: 10nF  Case/Package: 0603  Tolerance: 5%  [CAPC1608X90X40ML10T20]  (hidden comment: Capacitor 10nF +/- 5%, 50V, C0G, 0603)
C23  value 1µF  Tolerance: 10%  Voltage Rating: 16V  [CAPC1608X94X35NL15T15]  (hidden comment: Capacitor 1 uF +/- 10% 16 V 0603)
C24  Dielectric: C0G, NPO  Tolerance: 5%  Voltage Rating: 50V  Case/Package: 0603  Capacitance: 1nF  [CAPC1608X90X40ML10T20]  (hidden comment: Capacitor 1nF +/- 5%, 50V, C0G, 0603)
C25  value 100nF  Voltage Rating: 50V  [CAPC2013X95X50ML10T25]  (hidden comment: Capacitor 100 nF +/-10% 50 V 0805)
C26  Dielectric: C0G, NPO  Tolerance: 5%  Voltage Rating: 50V  Case/Package: 0603  Capacitance: 1nF  [CAPC1608X90X40ML10T20]  (hidden comment: Capacitor 1nF +/- 5%, 50V, C0G, 0603)
C27  value 100nF  Voltage Rating: 50V  [CAPC2013X95X50ML10T25]  (hidden comment: Capacitor 100 nF +/-10% 50 V 0805)
D5  1N4148WS  Case/Package: SOD-323  [FAIR-SOD-323_V]
R66  value 1.65k  Tolerance: 1%  Case/Package: 0603  [RESC1609X50X30ML08T20]  (hidden comment: Resistor 1K65 +/-1% 0603 100 mW)
R67  value 499  [RESC1609X50X30ML08T20]  (hidden comment: Resistor 499R +/-1% 0603 100 mW)
R68  value 332k  Tolerance: 1%  Case/Package: 0603  [RESC1609X50X30ML08T20]  (hidden comment: Resistor 332K +/-1% 0603 100 mW)
R69  value 1.65k  Tolerance: 1%  Case/Package: 0603  [RESC1609X50X30ML08T20]  (hidden comment: Resistor 1K65 +/-1% 0603 100 mW)
U7  TLV3202AIDR  [FP-D0008A-MFG]  (parts A,B of 2)
U8  SN74LVC1G17QDCKRQ1  [FP-DCK0005A-MFG]  (parts A,B of 2)

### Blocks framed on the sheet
F(-3dB)=100KHz LPF: C24 R66
F(-3dB)=100KHz LPF: C26 R69

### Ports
FAULT (out), FAULT-INJECT (in), GND, P5VIN, V_DELAY (in), V_ISET (in), V_ISNS (in)

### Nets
GND: C22.1 C23.1 C24.2 C25.1 C26.2 C27.1 U7.4(GND) U8.3(GND) ; port GND
P5V: C22.2 C23.2 C27.2 U7.8(VCC) U8.5(VCC) ; port P5VIN
FAULT: U8.4(Y) ; port FAULT
FAULT-INJECT: C24.1 R66.2 U7.2(1IN-) ; port FAULT-INJECT
V_DELAY: U7.6(2IN-) ; port V_DELAY
V_ISET: R66.1 ; port V_ISET
V_ISNS: R69.1 ; port V_ISNS
NetC25_2: C25.2 D5.1(A) R68.1 U7.5(2IN+)
NetC26_1: C26.1 R69.2 U7.3(1IN+)
NetD5_2: D5.2(K) R67.2
NetR67_1: R67.1 R68.2 U7.1(1OUT)
NetU7_7: U7.7(2OUT) U8.2(A)

Not connected (* = marked no-connect by the designer): U8 1(NC)*

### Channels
Input Current Limit/Current Limit - Configurable: designators end in _A; ports FAULT-INJECT=NetC24_A_1 FAULT=NetR41_2 GND=LV_GND P5VIN=LV_P5V V_DELAY=V_DELAY V_ISET=V_ISET V_ISNS=NetR69_A_1
Designator/Interface Channel A/Current Limit - Configurable: designators end in _B; ports FAULT-INJECT=FAULT-INJECT_Interface Channel A FAULT=ACTIVE-FAULT GND=LV_GND P5VIN=LV_P5V V_DELAY=V_DELAY_Interface Channel A V_ISET=CHA_CURRENT_SET V_ISNS=CH-I_Interface Channel A
Designator/Interface Channel B/Current Limit - Configurable: designators end in _C; ports FAULT-INJECT=FAULT-INJECT_Interface Channel B FAULT=ACTIVE-FAULT GND=LV_GND P5VIN=LV_P5V V_DELAY=V_DELAY_Interface Channel B V_ISET=CHB_CURRENT_SET V_ISNS=CH-I_Interface Channel B
Designator/Interface Channel C/Current Limit - Configurable: designators end in _D; ports FAULT-INJECT=FAULT-INJECT_Interface Channel C FAULT=ACTIVE-FAULT GND=LV_GND P5VIN=LV_P5V V_DELAY=V_DELAY_Interface Channel C V_ISET=CHC_CURRENT_SET V_ISNS=CH-I_Interface Channel C
Designator/Interface Channel D/Current Limit - Configurable: designators end in _E; ports FAULT-INJECT=FAULT-INJECT_Interface Channel D FAULT=ACTIVE-FAULT GND=LV_GND P5VIN=LV_P5V V_DELAY=V_DELAY_Interface Channel D V_ISET=CHD_CURRENT_SET V_ISNS=CH-I_Interface Channel D

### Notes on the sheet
- Place near Op-Amp VDD
- Fault Delay (RC Time Constant)
- 5V TTL
- TLV2452 is a nA input bias op-amp - Negligable input impedance bias error
- Discharge diode greatly increased discharge rate.
- (near C27) Place near Schmitt Trigger
- V_Delay Voltage Vs. Time (Approximate)

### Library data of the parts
C22 = CMP-001-00166-10: as C4 on sheet Input_Current_Limit
C23 = CMP-001-00003-15: as C5 on sheet Input_Current_Limit
C24 C26 = CMP-001-00153-10: as C3 on sheet Input_Current_Limit
C25 C27 = CMP-001-00018-16: as C2 on sheet Input_Current_Limit
D5 = CMP-004-00001-3: Small Signal Diode, 75 V, 0.15 A, -55 to 150 degC, 2-Pin SOD-323, RoHS, Tape and Reel; Manufacturer: Fairchild; Recovery Time: 4ns; Forward Voltage: 1V; Peak Reverse Current: 5uA; Forward Current: 150mA; Capacitance: -323f
R66 R69 = CMP-009-00807-5: Chip Resistor, 1.65k Ohm, +/- 1%, 0.1 W, -55 to 155 degC, 0603 (1608 Metric); Power: 100mW; Decade: 1k; Voltage Rating: 75V
R67 = CMP-009-00760-5: Chip Resistor, 499 Ohm, +/- 1%, 0.1 W, -55 to 155 degC, 0603 (1608 Metric); Power: 100mW; Decade: 100; Voltage Rating: 75V
R68 = CMP-009-00592-3: Chip Resistor, 332K Ohm, +/- 1%, 100 mW, -55 to 155 degC, 0603 (1608 Metric); Power: 100mW; Voltage Rating: 75V; Decade: 100k
U7 = CMP-014-00043-5: IC COMPARATOR RRI DUAL 8SOIC; Number of Channels: 2; Input Bias Current: 50pA; Max Supply Voltage: 5.5V; Min Supply Voltage: 2.7V; Input Offset Voltage (Vos): 5mV; Hysteresis: 1.2mV; Propagation Delay: 50ns; Max Supply Current: 40uA
U8 = CMP-016-00010-2: Automotive single 1.65-V to 6.5-V buffer with Schmitt-Trigger inputs 5-SC70 -40 to 125; Quiescent Current: 20uA; Min Supply Voltage: 1.65V; Number of Channels: 1; Output Type: PUSH-PULL; Turn-On Delay Time: 14ns; Logic Function: Schmitt Trigger,Buffer,Inverting; Max Supply Voltage: 5.5V; Propagation Delay: 8ns; Polarity: Non-Inverting

## Sheet 12V_to_5V_ISNS_REFOUT.SchDoc: MARS2 - IPB - 12V to 5V Clean Power
size 431 x 279 mm; Organization: ORGANIZATION; Address1: APPLIED PHYSICS LAB; Address2: UNIVERSITY OF WASHINGTON; Address3: 1013 NE 40TH STREET; Address4: SEATTLE, WA 98105; Revision: -; SheetNumber: 8; SheetTotal: 23; ENG_APP_DATE: --/--/--; DSN_APP_DATE: --/--/--; CHK_APP_DATE: --/--/--
Used 5 times, as channels Input Current Limit/12V to 5V (Linear) - ISNS Power, Designator/Interface Channel A/12V to 5V (Linear) - ISNS Power, Designator/Interface Channel B/12V to 5V (Linear) - ISNS Power, Designator/Interface Channel C/12V to 5V (Linear) - ISNS Power, Designator/Interface Channel D/12V to 5V (Linear) - ISNS Power. Parts and nets are listed once, with the designators drawn on the sheet.
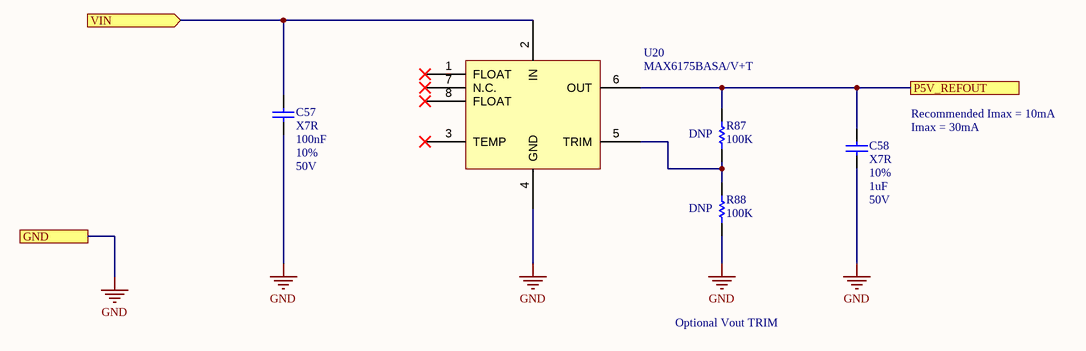
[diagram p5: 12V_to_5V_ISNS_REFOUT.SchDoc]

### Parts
C57  value 100nF  Dielectric: X7R  Tolerance: 10%  Voltage Rating: 50V  [CAPC1608X90X40ML10T20]  (hidden comment: Capacitor 100nF +/- 10%, 50V, X7R, 0603)
C58  value 1uF  Dielectric: X7R  Tolerance: 10%  Voltage Rating: 50V  [CAPC2013X95X50ML10T25]  (hidden comment: Capacitor 1uF 10%, 50V, X7R, 0805)
R87  value 100K  [RESC1609X50X30ML08T20]  (hidden comment: Resistor 100K +/-1% 0603 100 mW)
R88  value 100K  [RESC1609X50X30ML08T20]  (hidden comment: Resistor 100K +/-1% 0603 100 mW)
U20  MAX6175BASA/V+T  [SOIC127P600X175-8M]

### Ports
GND, P5V_REFOUT, VIN (in)

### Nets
GND: C57.1 C58.1 R88.1 U20.4(GND) ; port GND
P5V_REFOUT: C58.2 R87.2 U20.6(OUT) ; port P5V_REFOUT
VIN: C57.2 U20.2(IN) ; port VIN
NetR87_1: R87.1 R88.2 U20.5(TRIM)

Not connected (* = marked no-connect by the designer): U20 1(FLOAT)* 3(TEMP)* 7(N.C.)* 8(FLOAT)*

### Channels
Input Current Limit/12V to 5V (Linear) - ISNS Power: designators end in _A; ports GND=LV_GND P5V_REFOUT=LV_ISNS_P5V VIN=LV_ISNS_P12V
Designator/Interface Channel A/12V to 5V (Linear) - ISNS Power: designators end in _B; ports GND=LV_GND P5V_REFOUT=NetC10_B_1 VIN=LV_ISNS_P12V
Designator/Interface Channel B/12V to 5V (Linear) - ISNS Power: designators end in _C; ports GND=LV_GND P5V_REFOUT=NetC10_C_1 VIN=LV_ISNS_P12V
Designator/Interface Channel C/12V to 5V (Linear) - ISNS Power: designators end in _D; ports GND=LV_GND P5V_REFOUT=NetC10_D_1 VIN=LV_ISNS_P12V
Designator/Interface Channel D/12V to 5V (Linear) - ISNS Power: designators end in _E; ports GND=LV_GND P5V_REFOUT=NetC10_E_1 VIN=LV_ISNS_P12V

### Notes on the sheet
- (near R87) DNP
- Recommended Imax = 10mA
- Imax = 30mA
- (near R88) DNP
- Optional Vout TRIM

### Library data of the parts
C57 = CMP-001-00206-10: as C1 on sheet Top
C58 = CMP-001-00165-11: Chip Capacitor, 1uF, 10%, 50 V, X7R 0805 (2012 Metric); Capacitor Type: Ceramic
R87 R88 = CMP-009-01065-2: Chip Resistor, 100k Ohm, +/- 1%, 0.1 W, -55 to 155 degC, 0603 (1608 Metric); Power: 100mW; Voltage Rating: 75V
U20 = CMP-019-00065-5: MAX6175 Series 5.005V ±0.1 % Surface Mount SeriesVoltage Reference - SOIC-8. V+T is Automotive Quality.; Output Type: Fixed; Max Input Voltage: 42V; Tolerance: 0.1%; Temperature Coefficient: 10ppm/°C; Max Output Current: 30mA; Output Voltage: 5V; Operating Supply Current: 700uA

## Sheet FET_CH_Digital_Logic.SchDoc: MARS2 - IPB - Channel Digital Logic
size 431 x 279 mm; Organization: ORGANIZATION; Address1: APPLIED PHYSICS LAB; Address2: UNIVERSITY OF WASHINGTON; Address3: 1013 NE 40TH STREET; Address4: SEATTLE, WA 98105; Revision: -; SheetNumber: 7; SheetTotal: 23; ENG_APP_DATE: --/--/--; DSN_APP_DATE: --/--/--; CHK_APP_DATE: --/--/--
Used 5 times, as channels Input Current Limit/Channel Logic, Designator/Interface Channel A/Channel Logic, Designator/Interface Channel B/Channel Logic, Designator/Interface Channel C/Channel Logic, Designator/Interface Channel D/Channel Logic. Parts and nets are listed once, with the designators drawn on the sheet.
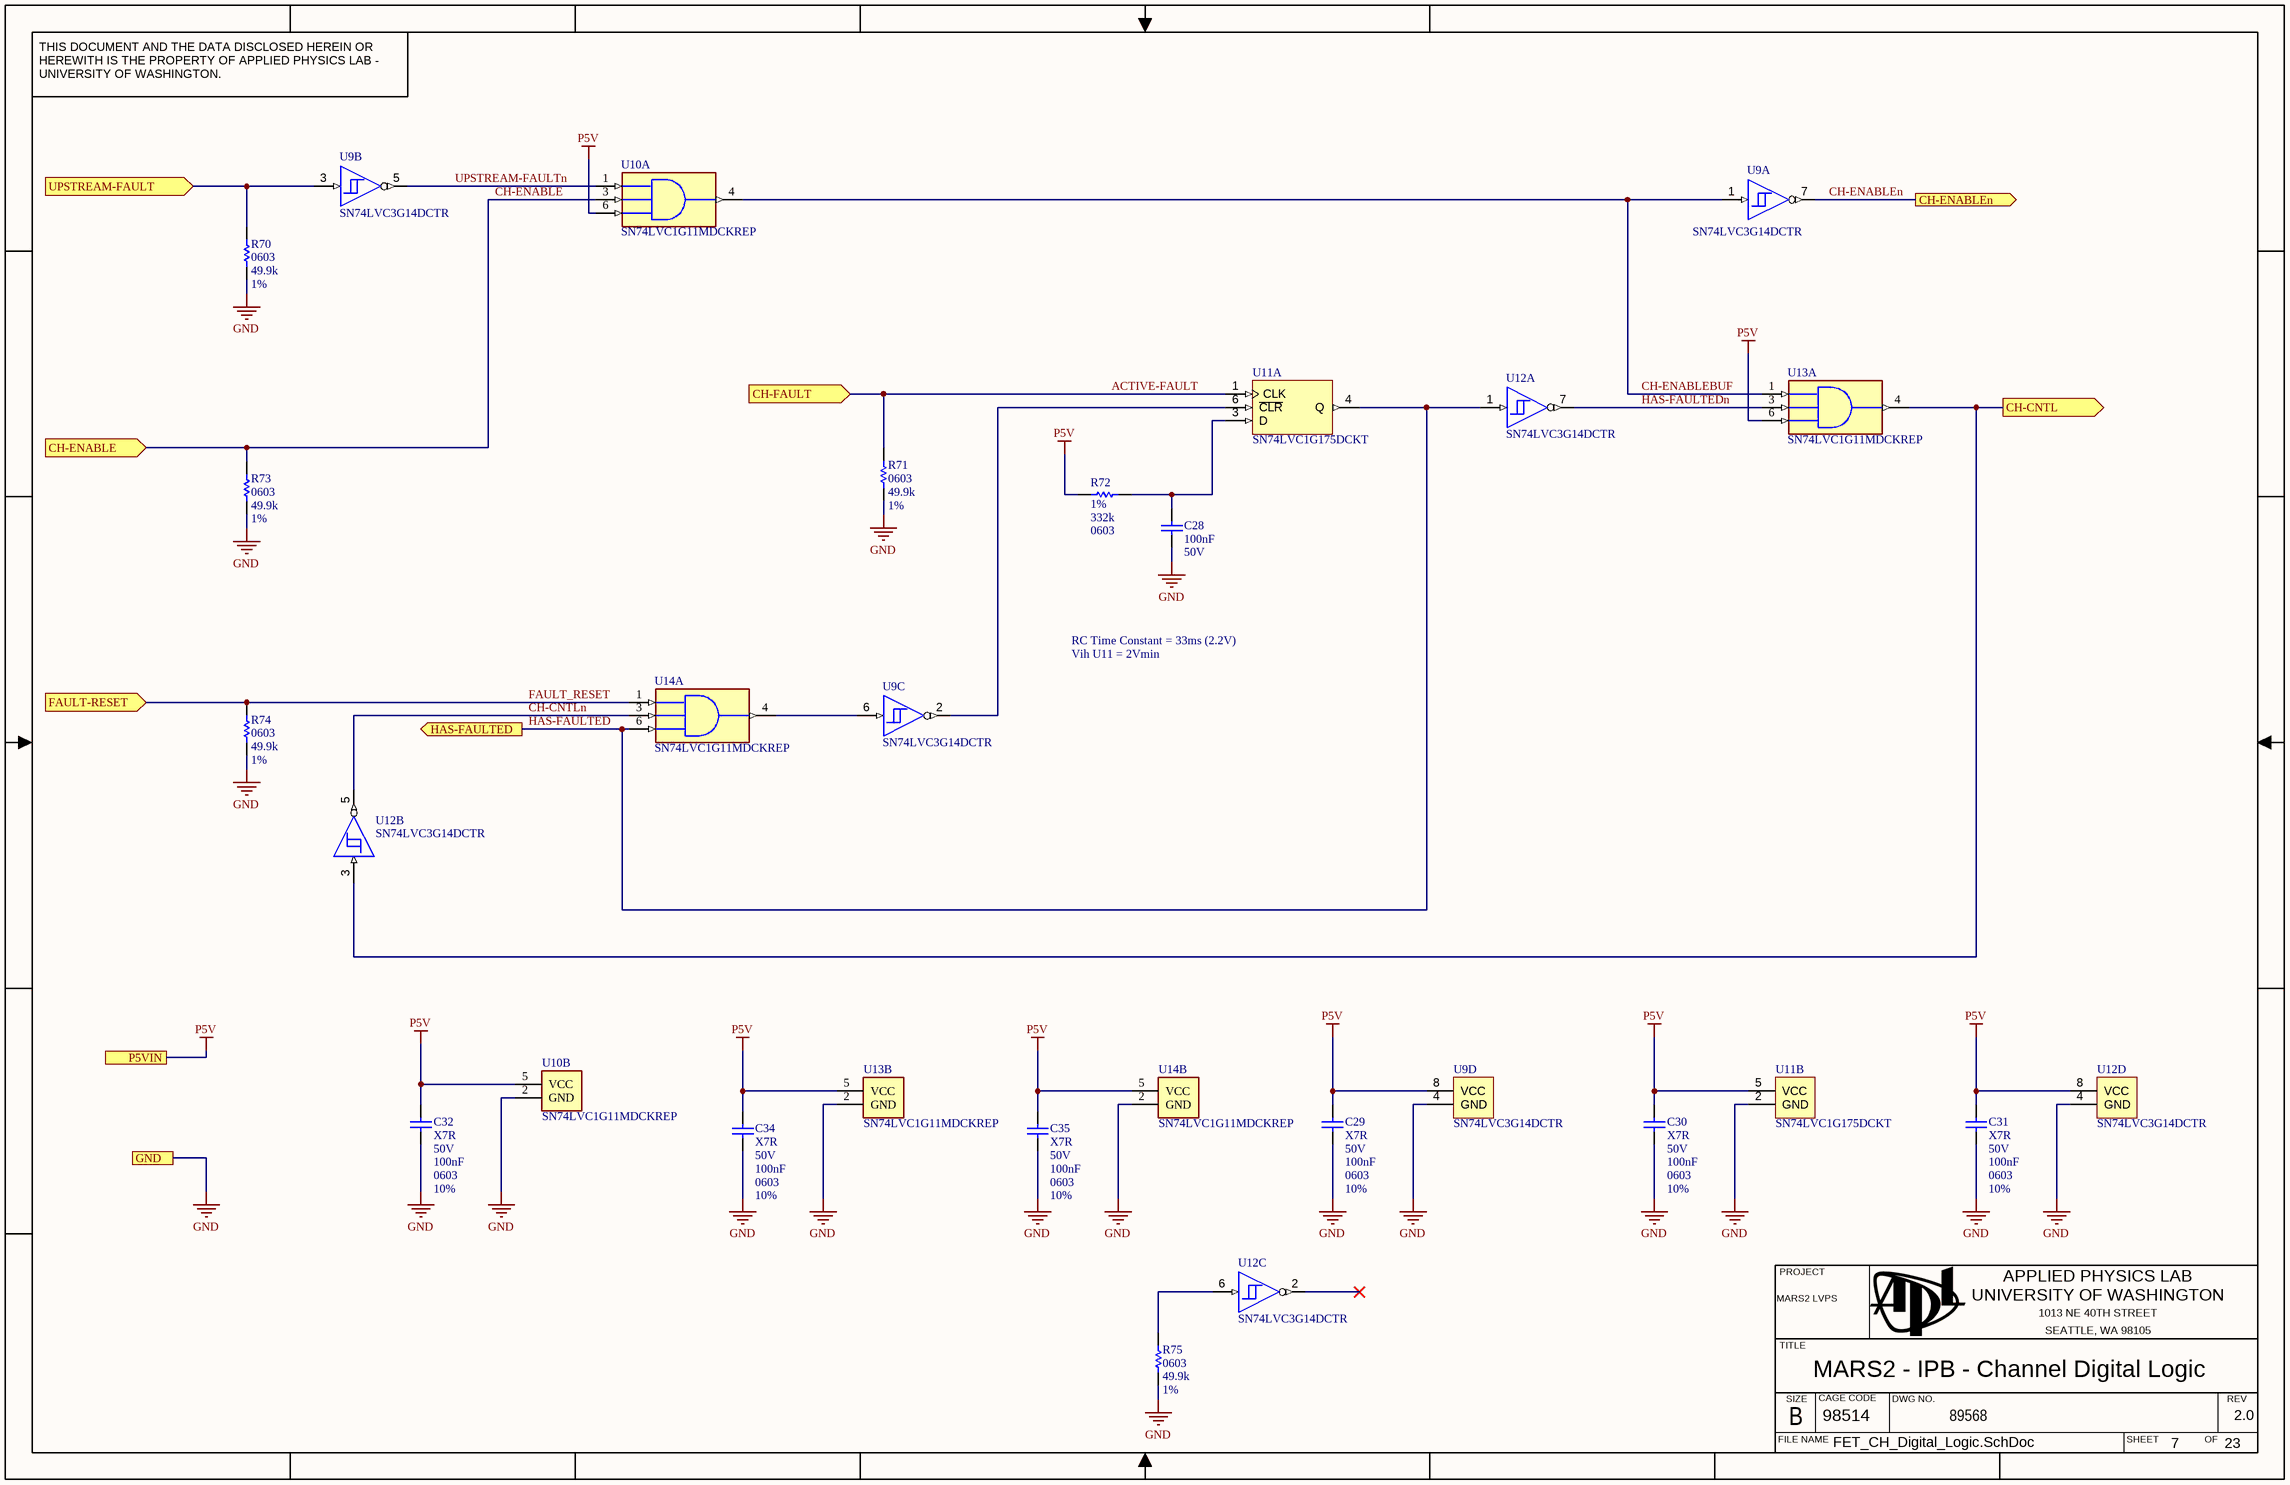
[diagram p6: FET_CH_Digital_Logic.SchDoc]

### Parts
C28  value 100nF  Voltage Rating: 50V  [CAPC2013X95X50ML10T25]  (hidden comment: Capacitor 100 nF +/-10% 50 V 0805)
C29  Dielectric: X7R  Voltage Rating: 50V  Capacitance: 100nF  Case/Package: 0603  Tolerance: 10%  [CAPC1608X90X40ML10T20]  (hidden comment: Capacitor 100nF +/- 10%, 50V, X7R, 0603)
C30  Dielectric: X7R  Voltage Rating: 50V  Capacitance: 100nF  Case/Package: 0603  Tolerance: 10%  [CAPC1608X90X40ML10T20]  (hidden comment: Capacitor 100nF +/- 10%, 50V, X7R, 0603)
C31  Dielectric: X7R  Voltage Rating: 50V  Capacitance: 100nF  Case/Package: 0603  Tolerance: 10%  [CAPC1608X90X40ML10T20]  (hidden comment: Capacitor 100nF +/- 10%, 50V, X7R, 0603)
C32  Dielectric: X7R  Voltage Rating: 50V  Capacitance: 100nF  Case/Package: 0603  Tolerance: 10%  [CAPC1608X90X40ML10T20]  (hidden comment: Capacitor 100nF +/- 10%, 50V, X7R, 0603)
C34  Dielectric: X7R  Voltage Rating: 50V  Capacitance: 100nF  Case/Package: 0603  Tolerance: 10%  [CAPC1608X90X40ML10T20]  (hidden comment: Capacitor 100nF +/- 10%, 50V, X7R, 0603)
C35  Dielectric: X7R  Voltage Rating: 50V  Capacitance: 100nF  Case/Package: 0603  Tolerance: 10%  [CAPC1608X90X40ML10T20]  (hidden comment: Capacitor 100nF +/- 10%, 50V, X7R, 0603)
R70  value 49.9k  Case/Package: 0603  Tolerance: 1%  [RESC1608X55X25ML10T15]  (hidden comment: Resistor 49K9 +/-1% 0603 100 mW)
R71  value 49.9k  Case/Package: 0603  Tolerance: 1%  [RESC1608X55X25ML10T15]  (hidden comment: Resistor 49K9 +/-1% 0603 100 mW)
R72  value 332k  Tolerance: 1%  Case/Package: 0603  [RESC1609X50X30ML08T20]  (hidden comment: Resistor 332K +/-1% 0603 100 mW)
R73  value 49.9k  Case/Package: 0603  Tolerance: 1%  [RESC1608X55X25ML10T15]  (hidden comment: Resistor 49K9 +/-1% 0603 100 mW)
R74  value 49.9k  Case/Package: 0603  Tolerance: 1%  [RESC1608X55X25ML10T15]  (hidden comment: Resistor 49K9 +/-1% 0603 100 mW)
R75  value 49.9k  Case/Package: 0603  Tolerance: 1%  [RESC1608X55X25ML10T15]  (hidden comment: Resistor 49K9 +/-1% 0603 100 mW)
U9  SN74LVC3G14DCTR  [DCT0008A_M]  (parts A,B,C,D of 4)
U10  SN74LVC1G11MDCKREP  [FP-DCK0006A-MFG]  (parts A,B of 2)
U11  SN74LVC1G175DCKT  [DCK0006A_M]  (parts A,B of 2)
U12  SN74LVC3G14DCTR  [DCT0008A_M]  (parts A,B,C,D of 4)
U13  SN74LVC1G11MDCKREP  [FP-DCK0006A-MFG]  (parts A,B of 2)
U14  SN74LVC1G11MDCKREP  [FP-DCK0006A-MFG]  (parts A,B of 2)

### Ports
CH-CNTL (out), CH-ENABLE (in), CH-ENABLEn (out), CH-FAULT (in), FAULT-RESET (in), GND, HAS-FAULTED (out), P5VIN, UPSTREAM-FAULT (in)

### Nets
GND: C28.1 C29.1 C30.1 C31.1 C32.1 C34.1 C35.1 R70.1 R71.1 R73.1 R74.1 R75.1 U9.4(GND) U10.2(GND) U11.2(GND) U12.4(GND) U13.2(GND) U14.2(GND) ; port GND
P5V: C29.2 C30.2 C31.2 C32.2 C34.2 C35.2 R72.2 U9.8(VCC) U10.5(VCC) U10.6(C) U11.5(VCC) U12.8(VCC) U13.5(VCC) U13.6(C) U14.5(VCC) ; port P5VIN
ACTIVE-FAULT: R71.2 U11.1(CLK) ; port CH-FAULT
CH-CNTL: U12.3(2A) U13.4(Y) ; port CH-CNTL
CH-CNTLn: U12.5(2Y) U14.3(B)  [project net CH-CNTLn_7]
CH-ENABLE: R73.2 U10.3(B) ; port CH-ENABLE
CH-ENABLEBUF: U9.1(1A) U10.4(Y) U13.1(A)  [project net CH-ENABLEBUF_7]
CH-ENABLEn: U9.7(1Y) ; port CH-ENABLEn
FAULT_RESET: R74.2 U14.1(A) ; port FAULT-RESET
HAS-FAULTED: U11.4(Q) U12.1(1A) U14.6(C) ; port HAS-FAULTED
HAS-FAULTEDn: U12.7(1Y) U13.3(B)  [project net HAS-FAULTEDn_7]
UPSTREAM-FAULT: R70.2 U9.3(2A) ; port UPSTREAM-FAULT
UPSTREAM-FAULTn: U9.5(2Y) U10.1(A)  [project net UPSTREAM-FAULTn_7]
NetC28_2: C28.2 R72.1 U11.3(D)
NetR75_2: R75.2 U12.6(3A)
NetU9_2: U9.2(3Y) U11.6(~{CLR})
NetU9_6: U9.6(3A) U14.4(Y)

Not connected (* = marked no-connect by the designer): U12 2(3Y)*

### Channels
Input Current Limit/Channel Logic: designators end in _A; ports CH-CNTL=NetU12_A_3 CH-ENABLE=CH-ENABLE CH-ENABLEn=CH-ENABLEn_Channel Logic CH-FAULT=ACTIVE-FAULT FAULT-RESET=INPUT-FAULT-RESET GND=LV_GND HAS-FAULTED=FAULT_SENSE_IN0 P5VIN=LV_P5V UPSTREAM-FAULT=NetR70_A_2
Designator/Interface Channel A/Channel Logic: designators end in _B; ports CH-CNTL=NetR63_A_1 CH-ENABLE=CHA_FET_EN CH-ENABLEn=CH-ENABLEn_Channel Logic CH-FAULT=ACTIVE-FAULT FAULT-RESET=CH-ENABLEn_Channel Logic GND=LV_GND HAS-FAULTED=FAULT_SENSE_IN1 P5VIN=LV_P5V UPSTREAM-FAULT=FAULT_SENSE_IN0
Designator/Interface Channel B/Channel Logic: designators end in _C; ports CH-CNTL=NetR63_B_1 CH-ENABLE=CHB_FET_EN CH-ENABLEn=CH-ENABLEn_Channel Logic CH-FAULT=ACTIVE-FAULT FAULT-RESET=CH-ENABLEn_Channel Logic GND=LV_GND HAS-FAULTED=FAULT_SENSE_IN2 P5VIN=LV_P5V UPSTREAM-FAULT=FAULT_SENSE_IN0
Designator/Interface Channel C/Channel Logic: designators end in _D; ports CH-CNTL=NetR63_C_1 CH-ENABLE=CHC_FET_EN CH-ENABLEn=CH-ENABLEn_Channel Logic CH-FAULT=ACTIVE-FAULT FAULT-RESET=CH-ENABLEn_Channel Logic GND=LV_GND HAS-FAULTED=FAULT_SENSE_IN3 P5VIN=LV_P5V UPSTREAM-FAULT=FAULT_SENSE_IN0
Designator/Interface Channel D/Channel Logic: designators end in _E; ports CH-CNTL=NetR63_D_1 CH-ENABLE=CHD_FET_EN CH-ENABLEn=CH-ENABLEn_Channel Logic CH-FAULT=ACTIVE-FAULT FAULT-RESET=CH-ENABLEn_Channel Logic GND=LV_GND HAS-FAULTED=FAULT_SENSE_IN4 P5VIN=LV_P5V UPSTREAM-FAULT=FAULT_SENSE_IN0

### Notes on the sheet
- RC Time Constant = 33ms (2.2V)
- Vih U11 = 2Vmin

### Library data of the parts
C28 = CMP-001-00018-16: as C2 on sheet Input_Current_Limit
C29-C32 C34 C35 = CMP-001-00206-10: as C1 on sheet Top
R70 R71 R73-R75 = CMP-009-01001-4: Chip Resistor, 49.9k Ohm, +/- 1%, 0.1 W, -55 to 155 degC, 0603 (1608 Metric); Power: 100mW; Voltage Rating: 75V; Decade: 10k
R72 = CMP-009-00592-3: as R68 on sheet Analog_Current_Limit
U9 = CMP-016-00017-2: Inverter IC 3 Channel Schmitt Trigger SM8; Schmitt Trigger Input: Yes; Propagation Delay: 4.3ns; Min Supply Voltage: 1.65V; Number of Circuits: 3; Max Supply Voltage: 5.5V; Output Current: 32mA; Logic Function: Inverter,Schmitt Trigger
U10 U13 U14 = CMP-016-00015-3: Enhanced product single 3-input, 1.65-V to 5.5-V AND gate 6-SC70 -55 to 125; Propagation Delay: 5ns; Number of Circuits: 1; Min Supply Voltage: 1.65V; Quiescent Current: 10uA; Max Supply Voltage: 5.5V
U11 = CMP-016-00016-2: Single D-Type Flip-Flop with Asynchronous Clear 6-SC70 -40 to 125; Output Current: 32mA; Min Supply Voltage: 1.65V; Max Supply Voltage: 5.5V; Clock Edge Trigger Type: Positive Edge; Number of Circuits: 1; Polarity: Non-Inverting; Frequency: 175MHz
U12 = CMP-016-00017-2: Inverter IC 3 Channel Schmitt Trigger SM8; Number of Circuits: 3; Propagation Delay: 4.3ns; Output Current: 32mA; Schmitt Trigger Input: Yes; Logic Function: Inverter,Schmitt Trigger; Min Supply Voltage: 1.65V; Max Supply Voltage: 5.5V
